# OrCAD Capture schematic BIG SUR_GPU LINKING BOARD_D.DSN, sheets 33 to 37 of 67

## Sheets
33 P33  PCIe x16 Slot-2: size C
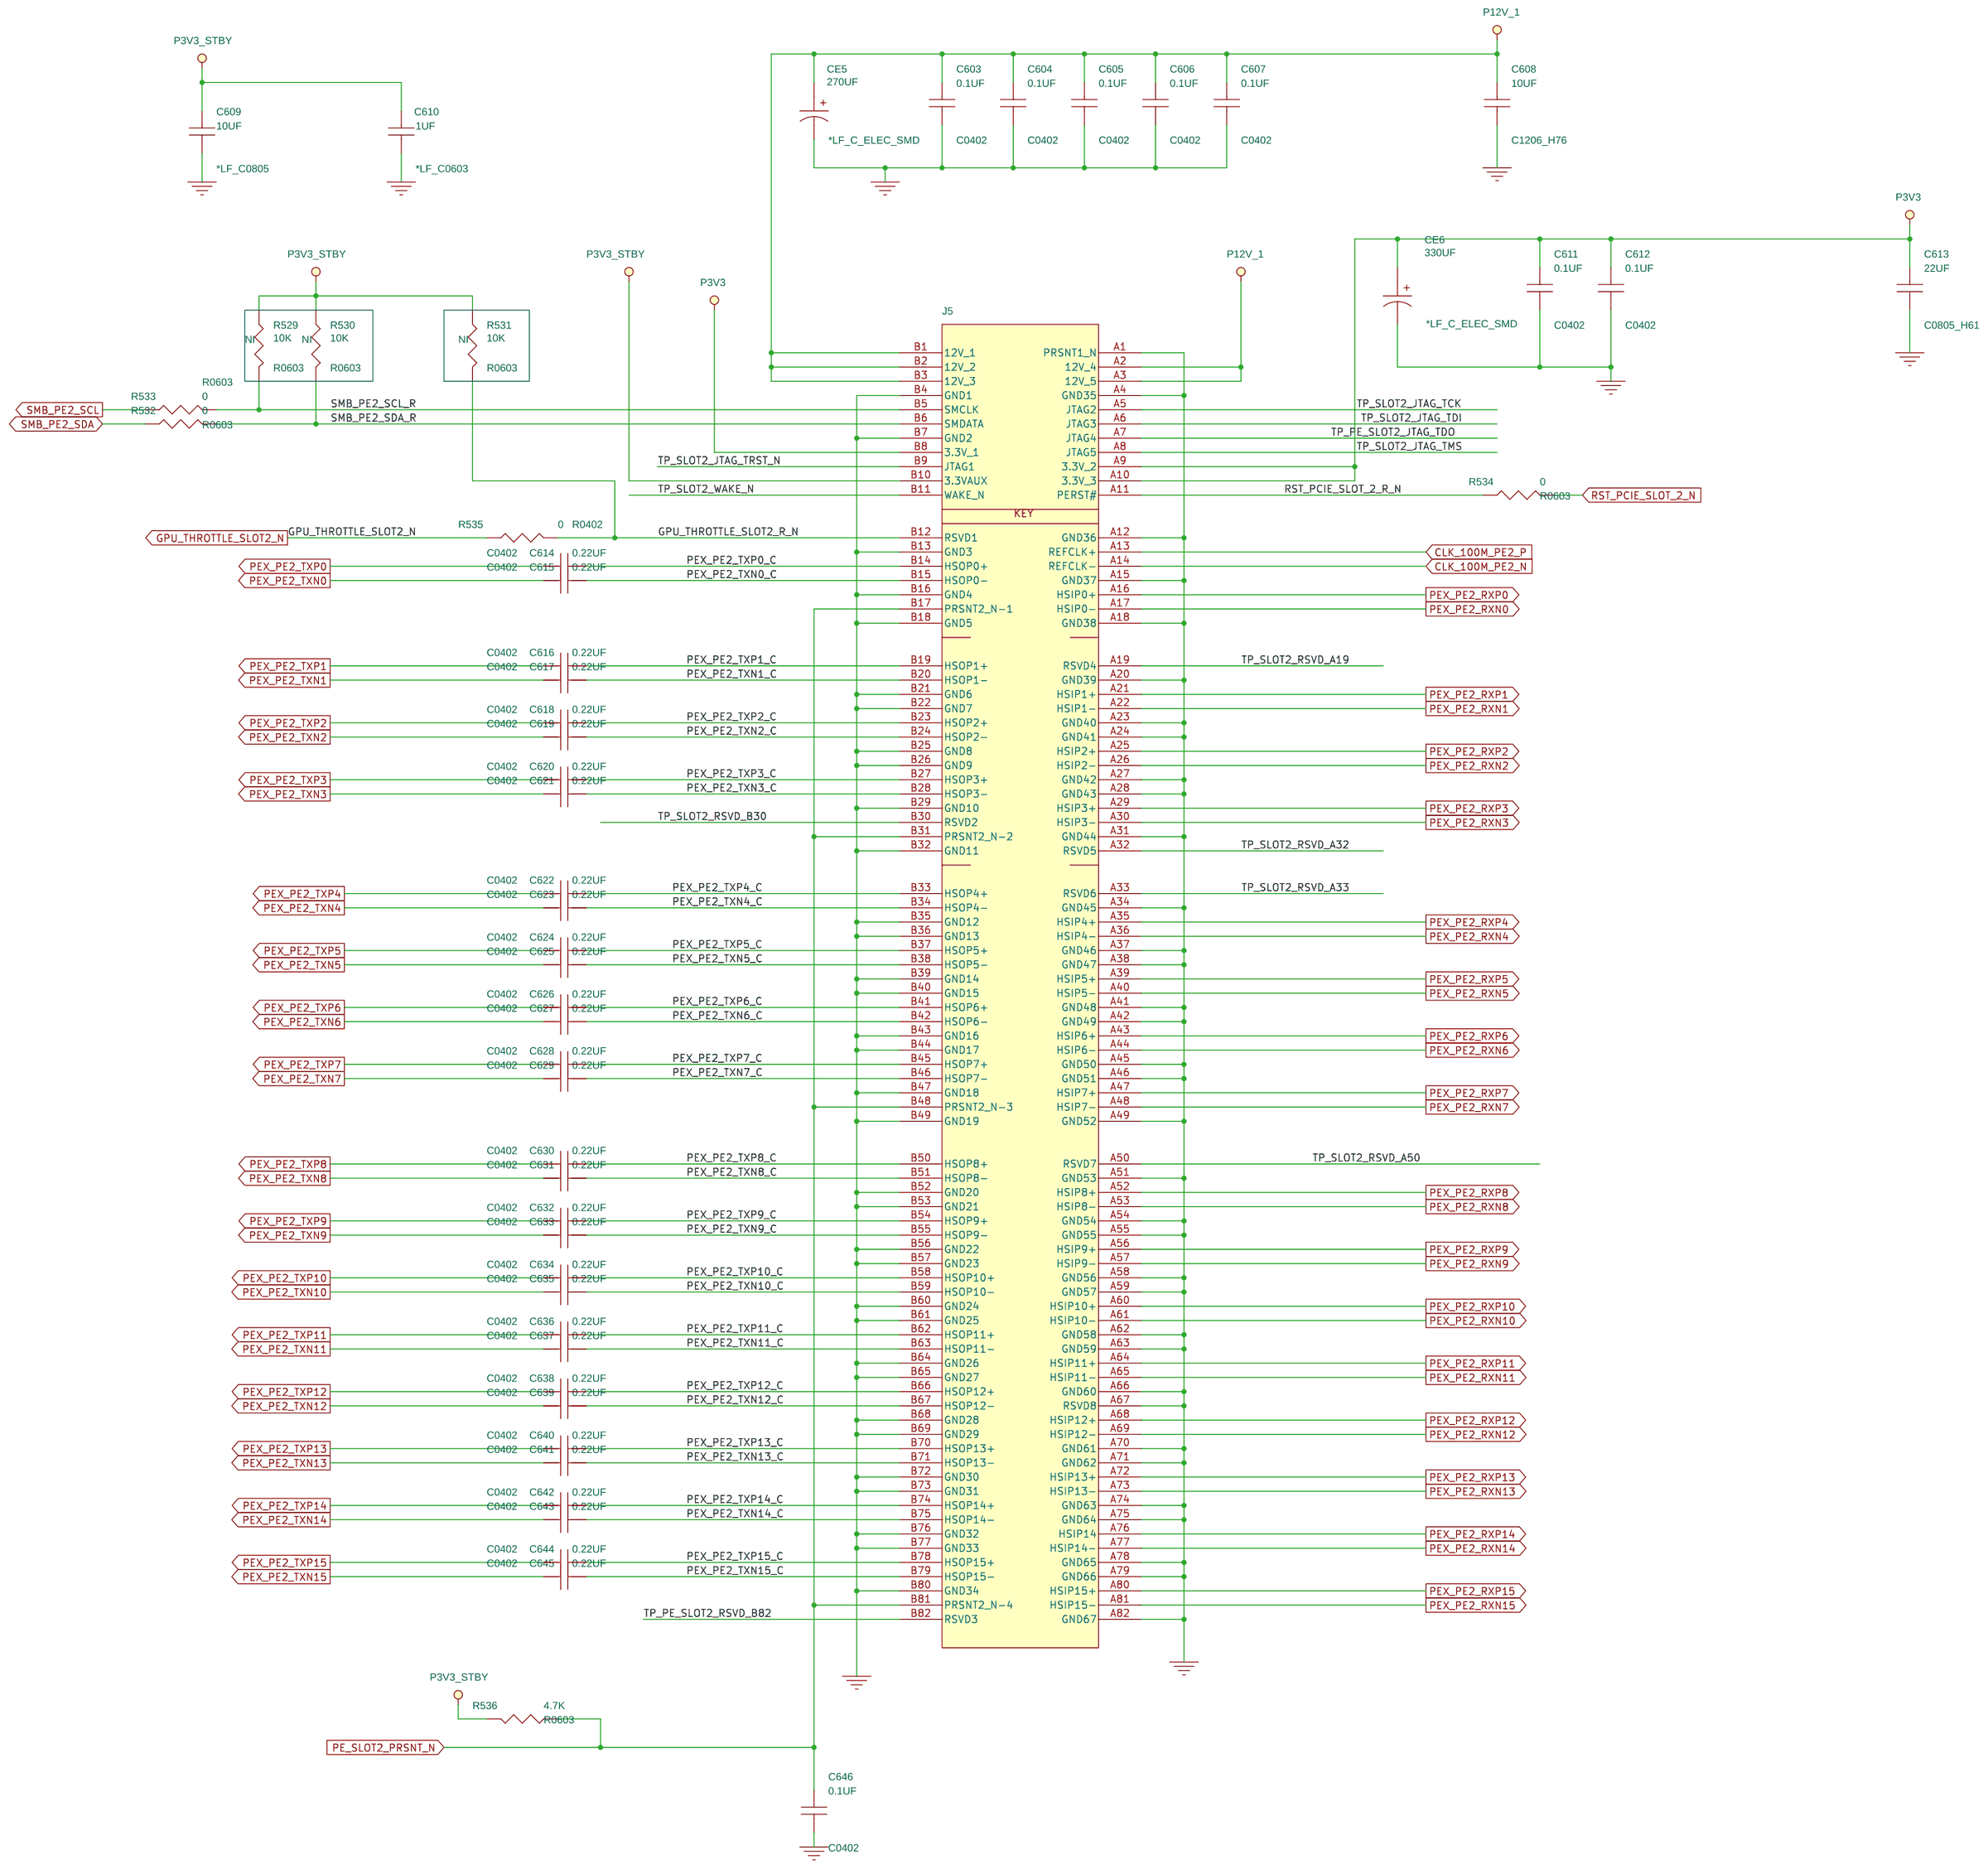
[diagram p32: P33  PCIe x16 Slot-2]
34 P34  PCIe x16 Slot-3: size C
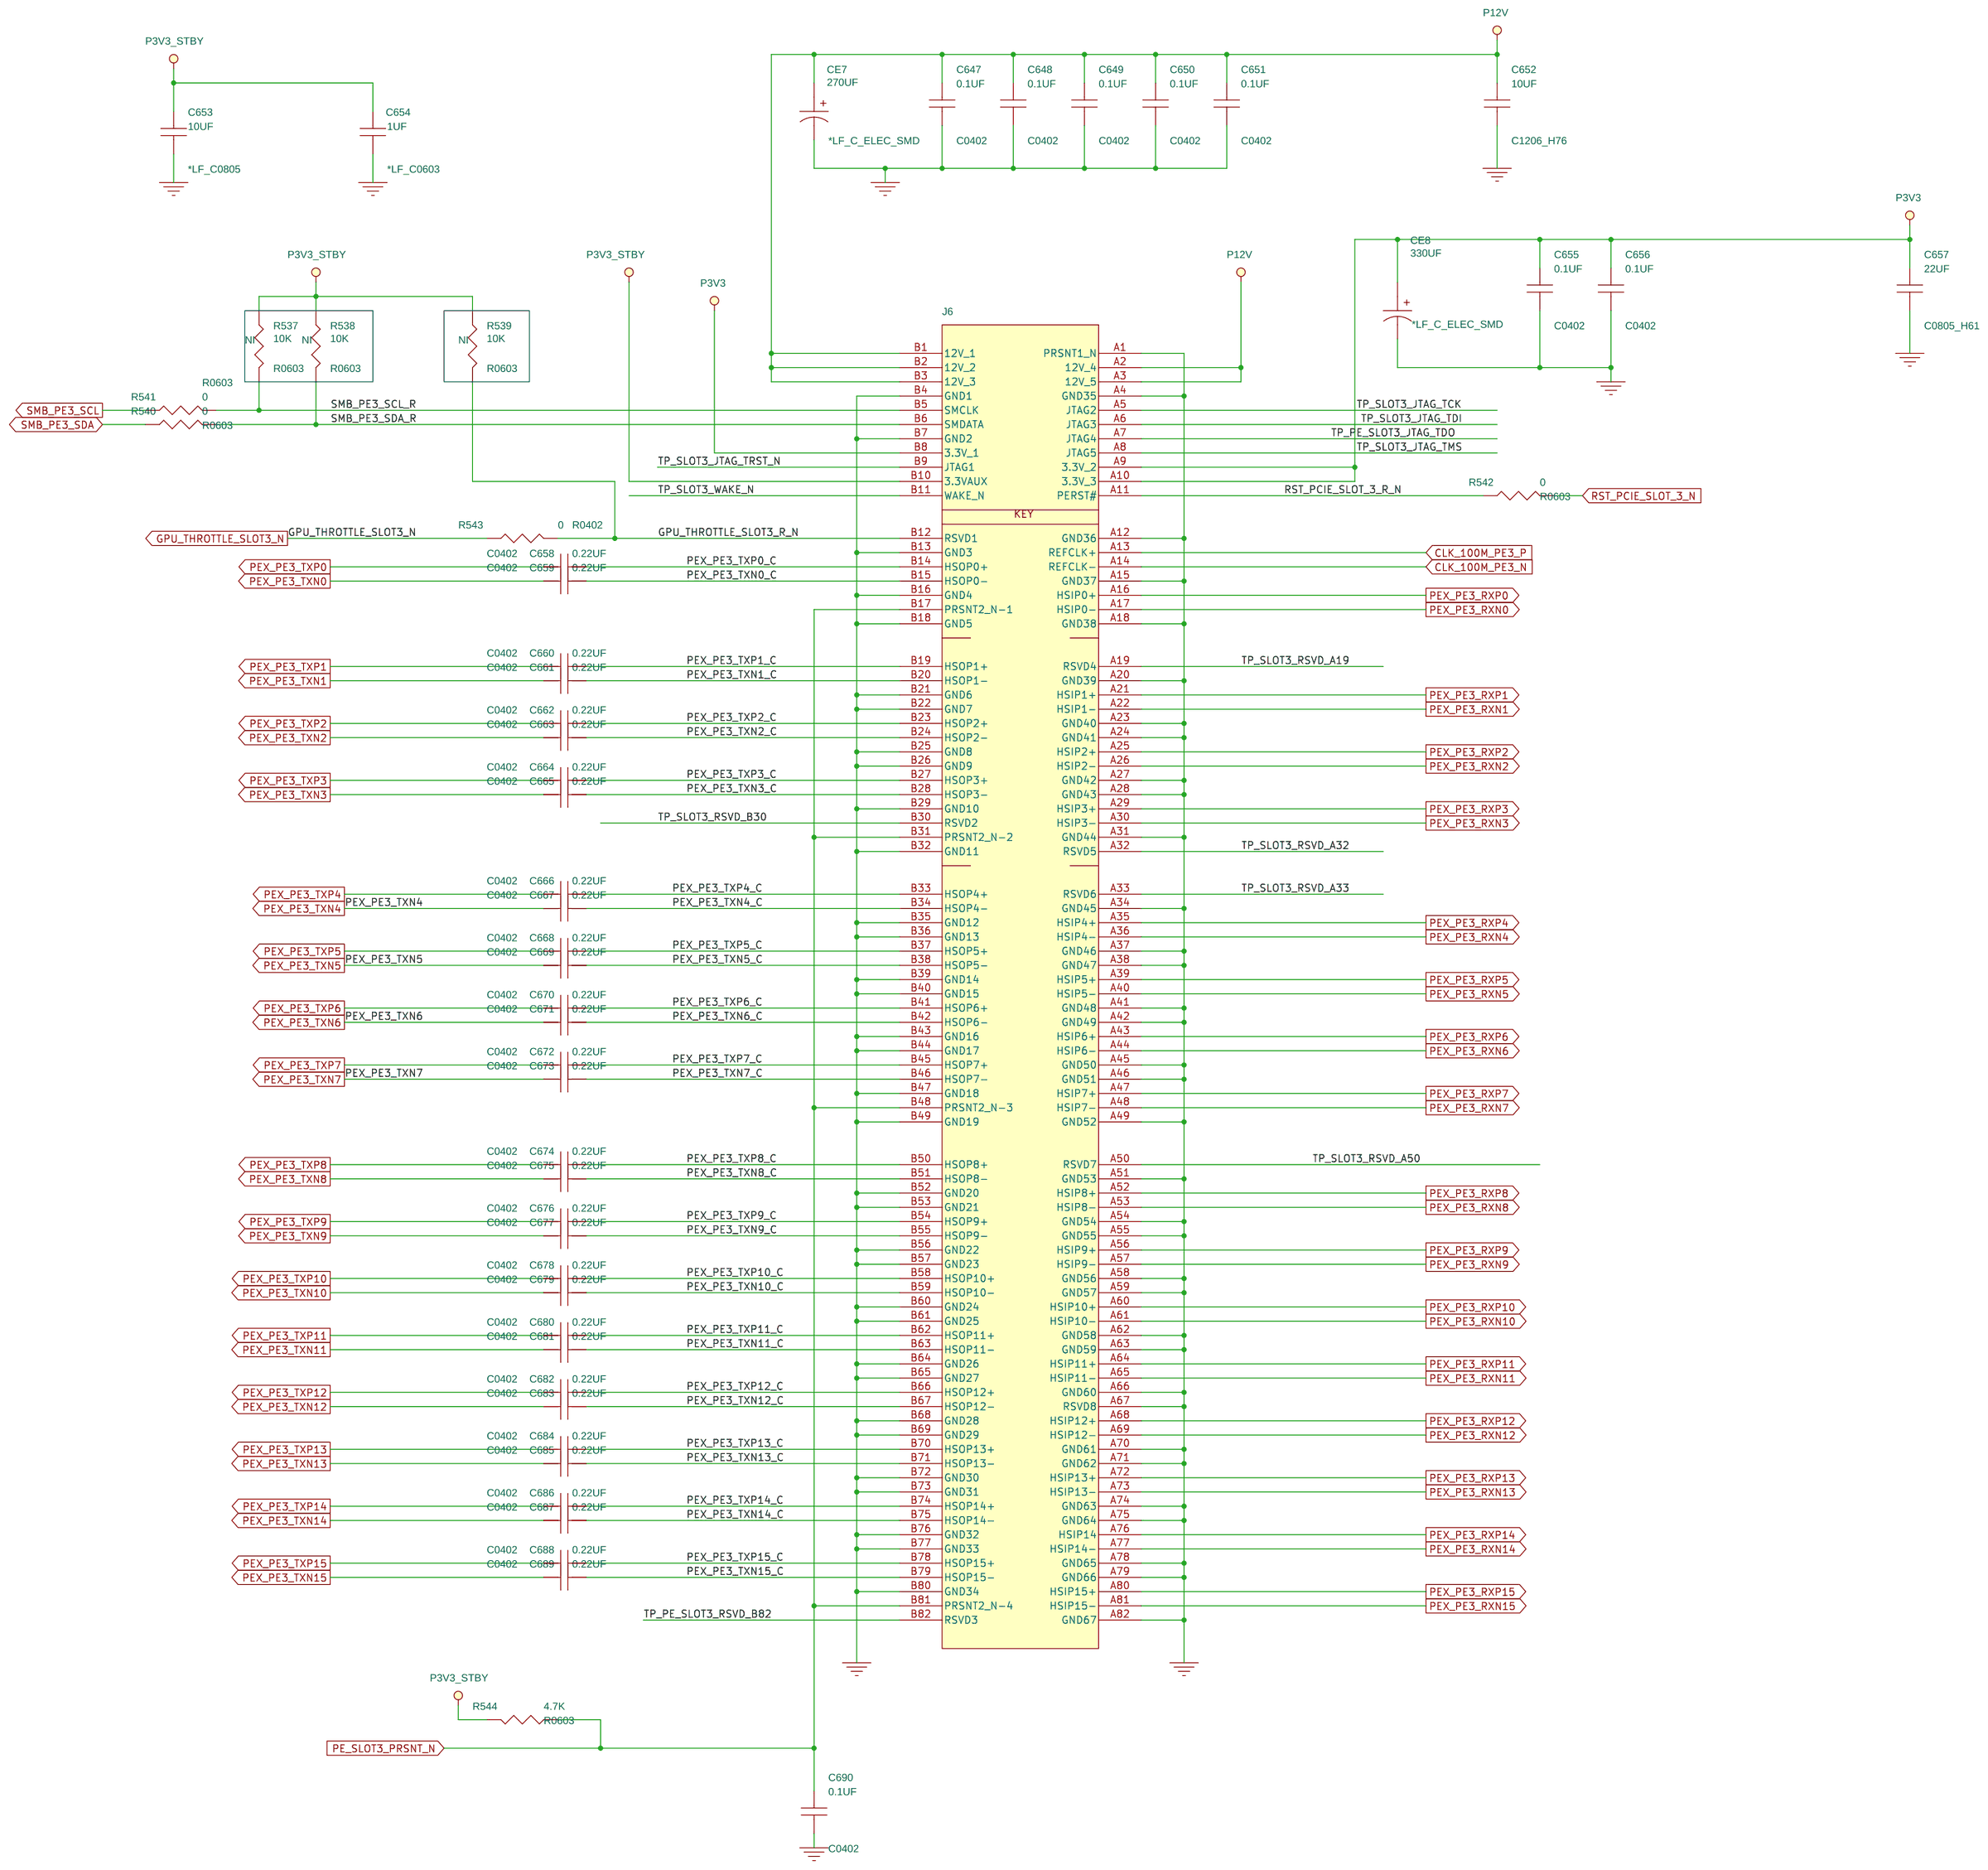
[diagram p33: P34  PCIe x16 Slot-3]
35 P35  PCIe x16 Slot-4: size C
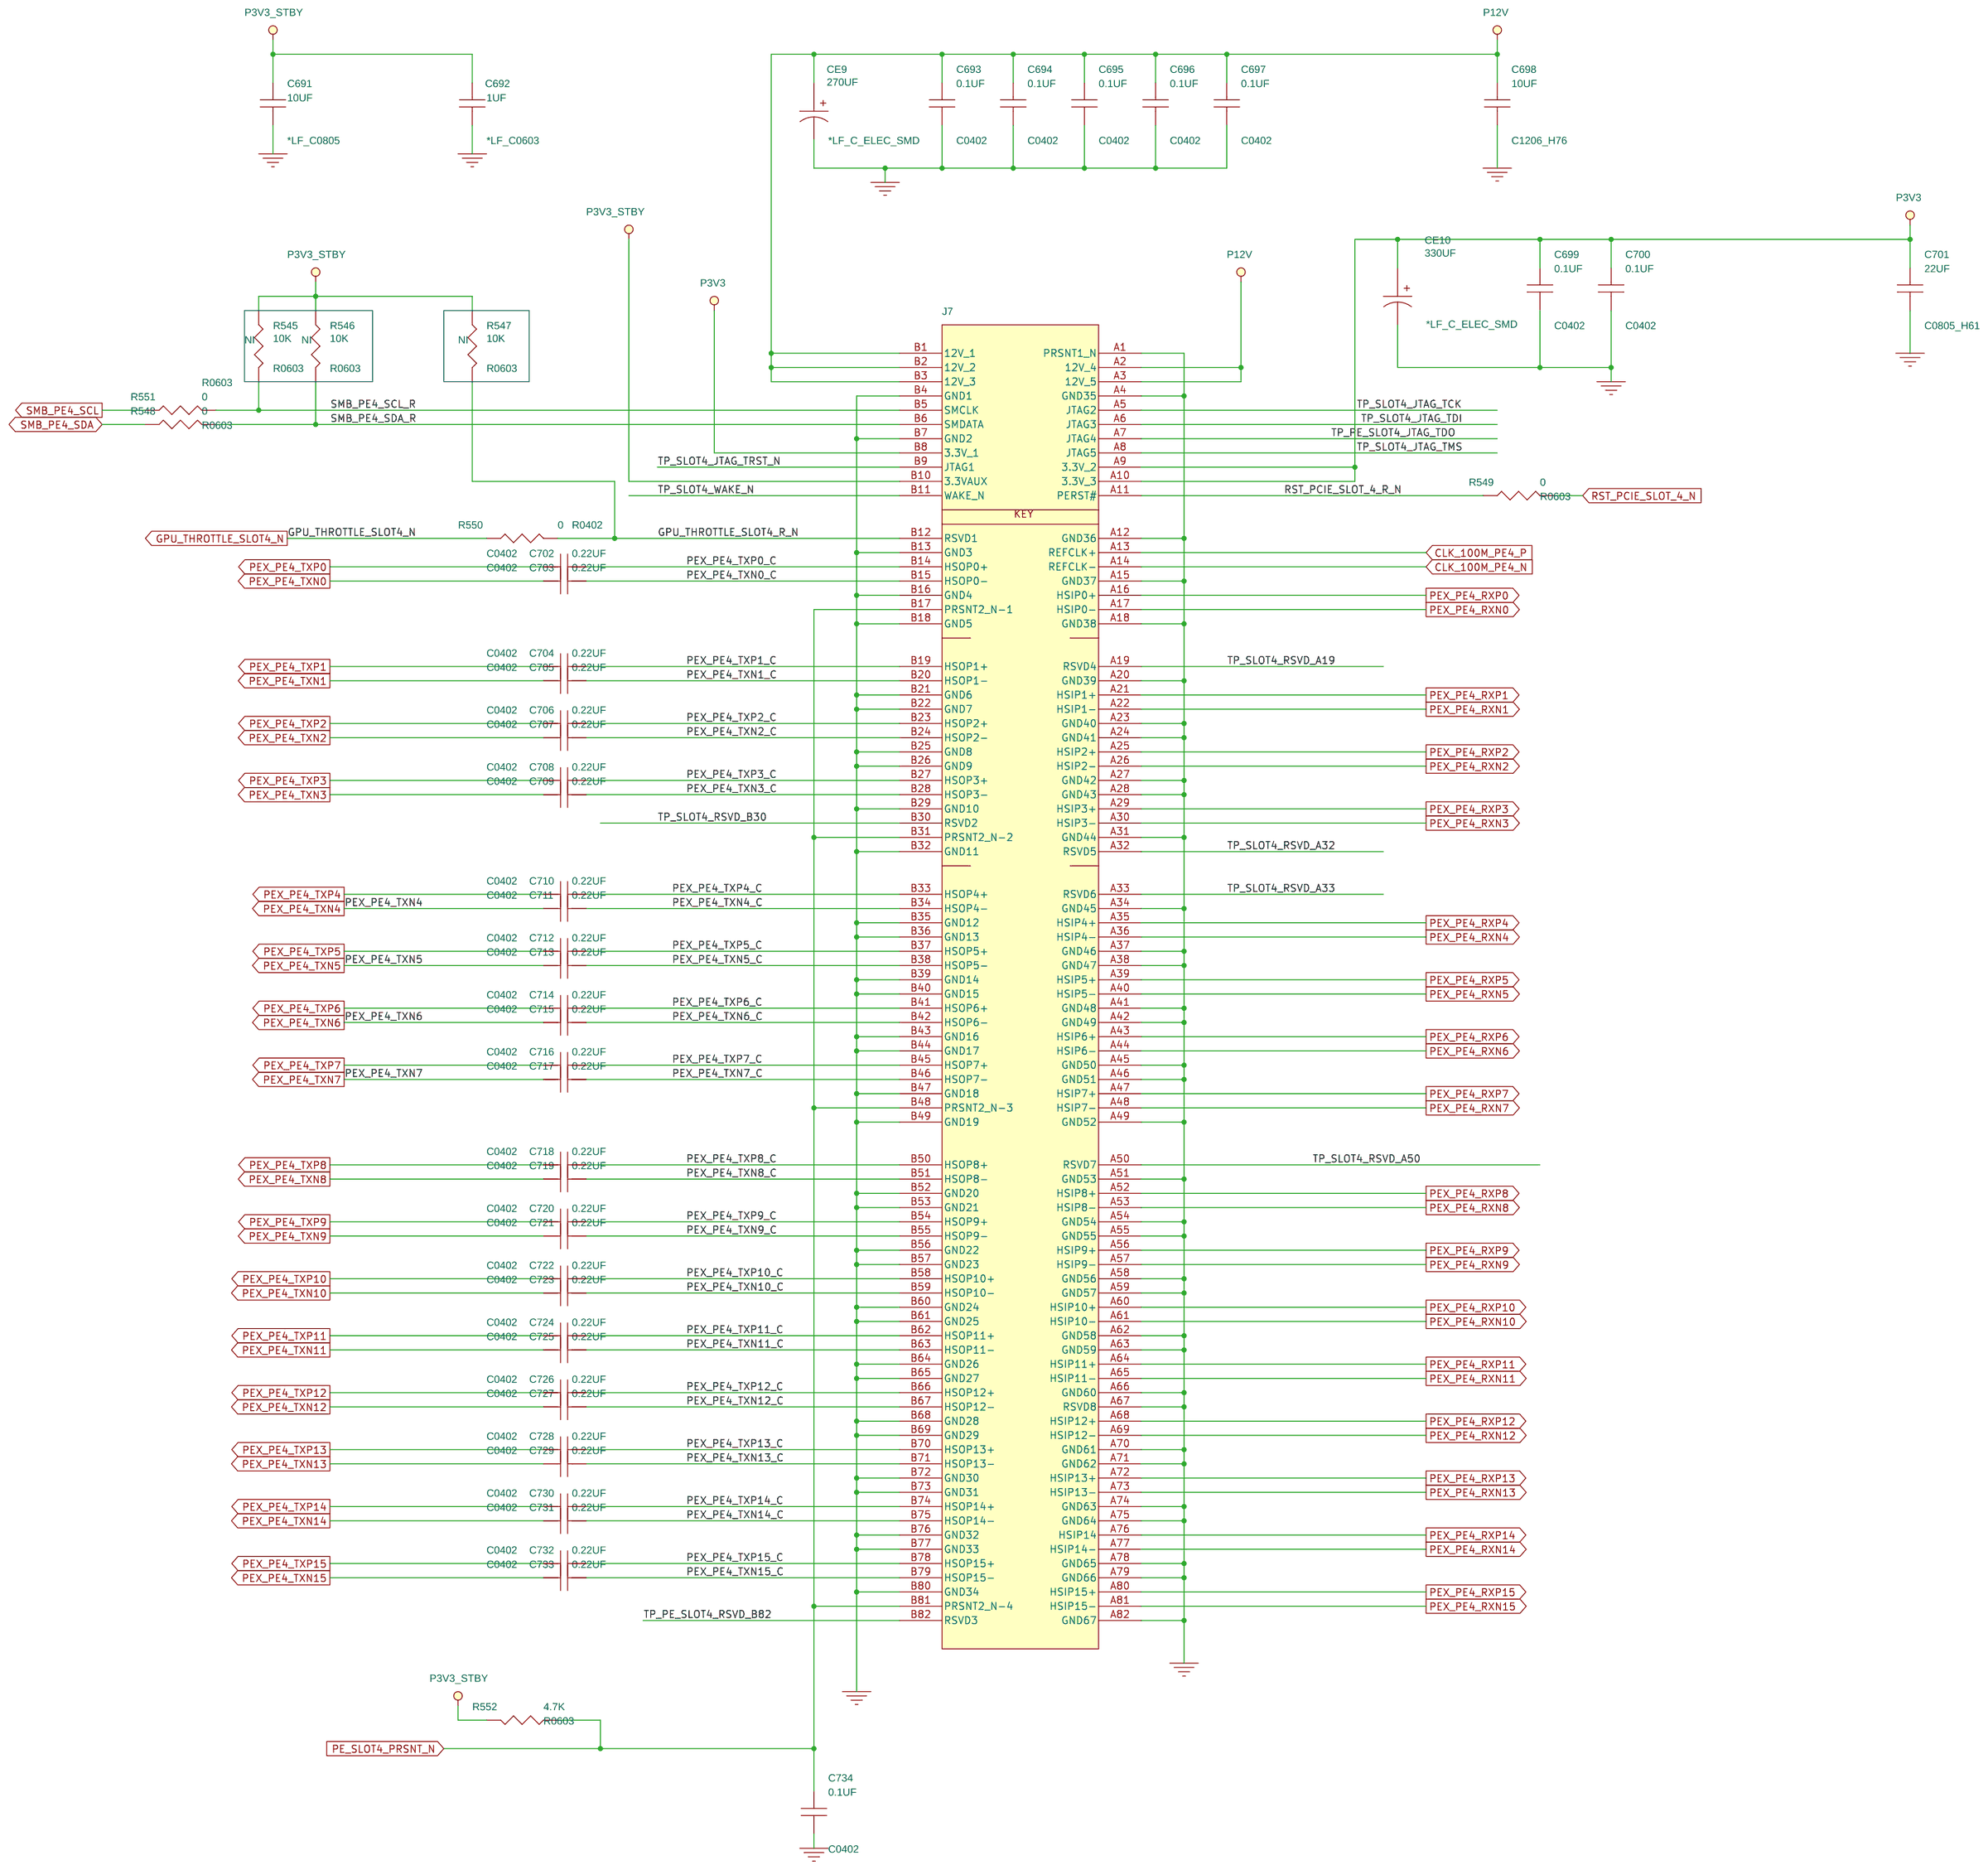
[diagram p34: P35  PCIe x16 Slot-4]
36 P36  PCIe x16 Slot-5: size C
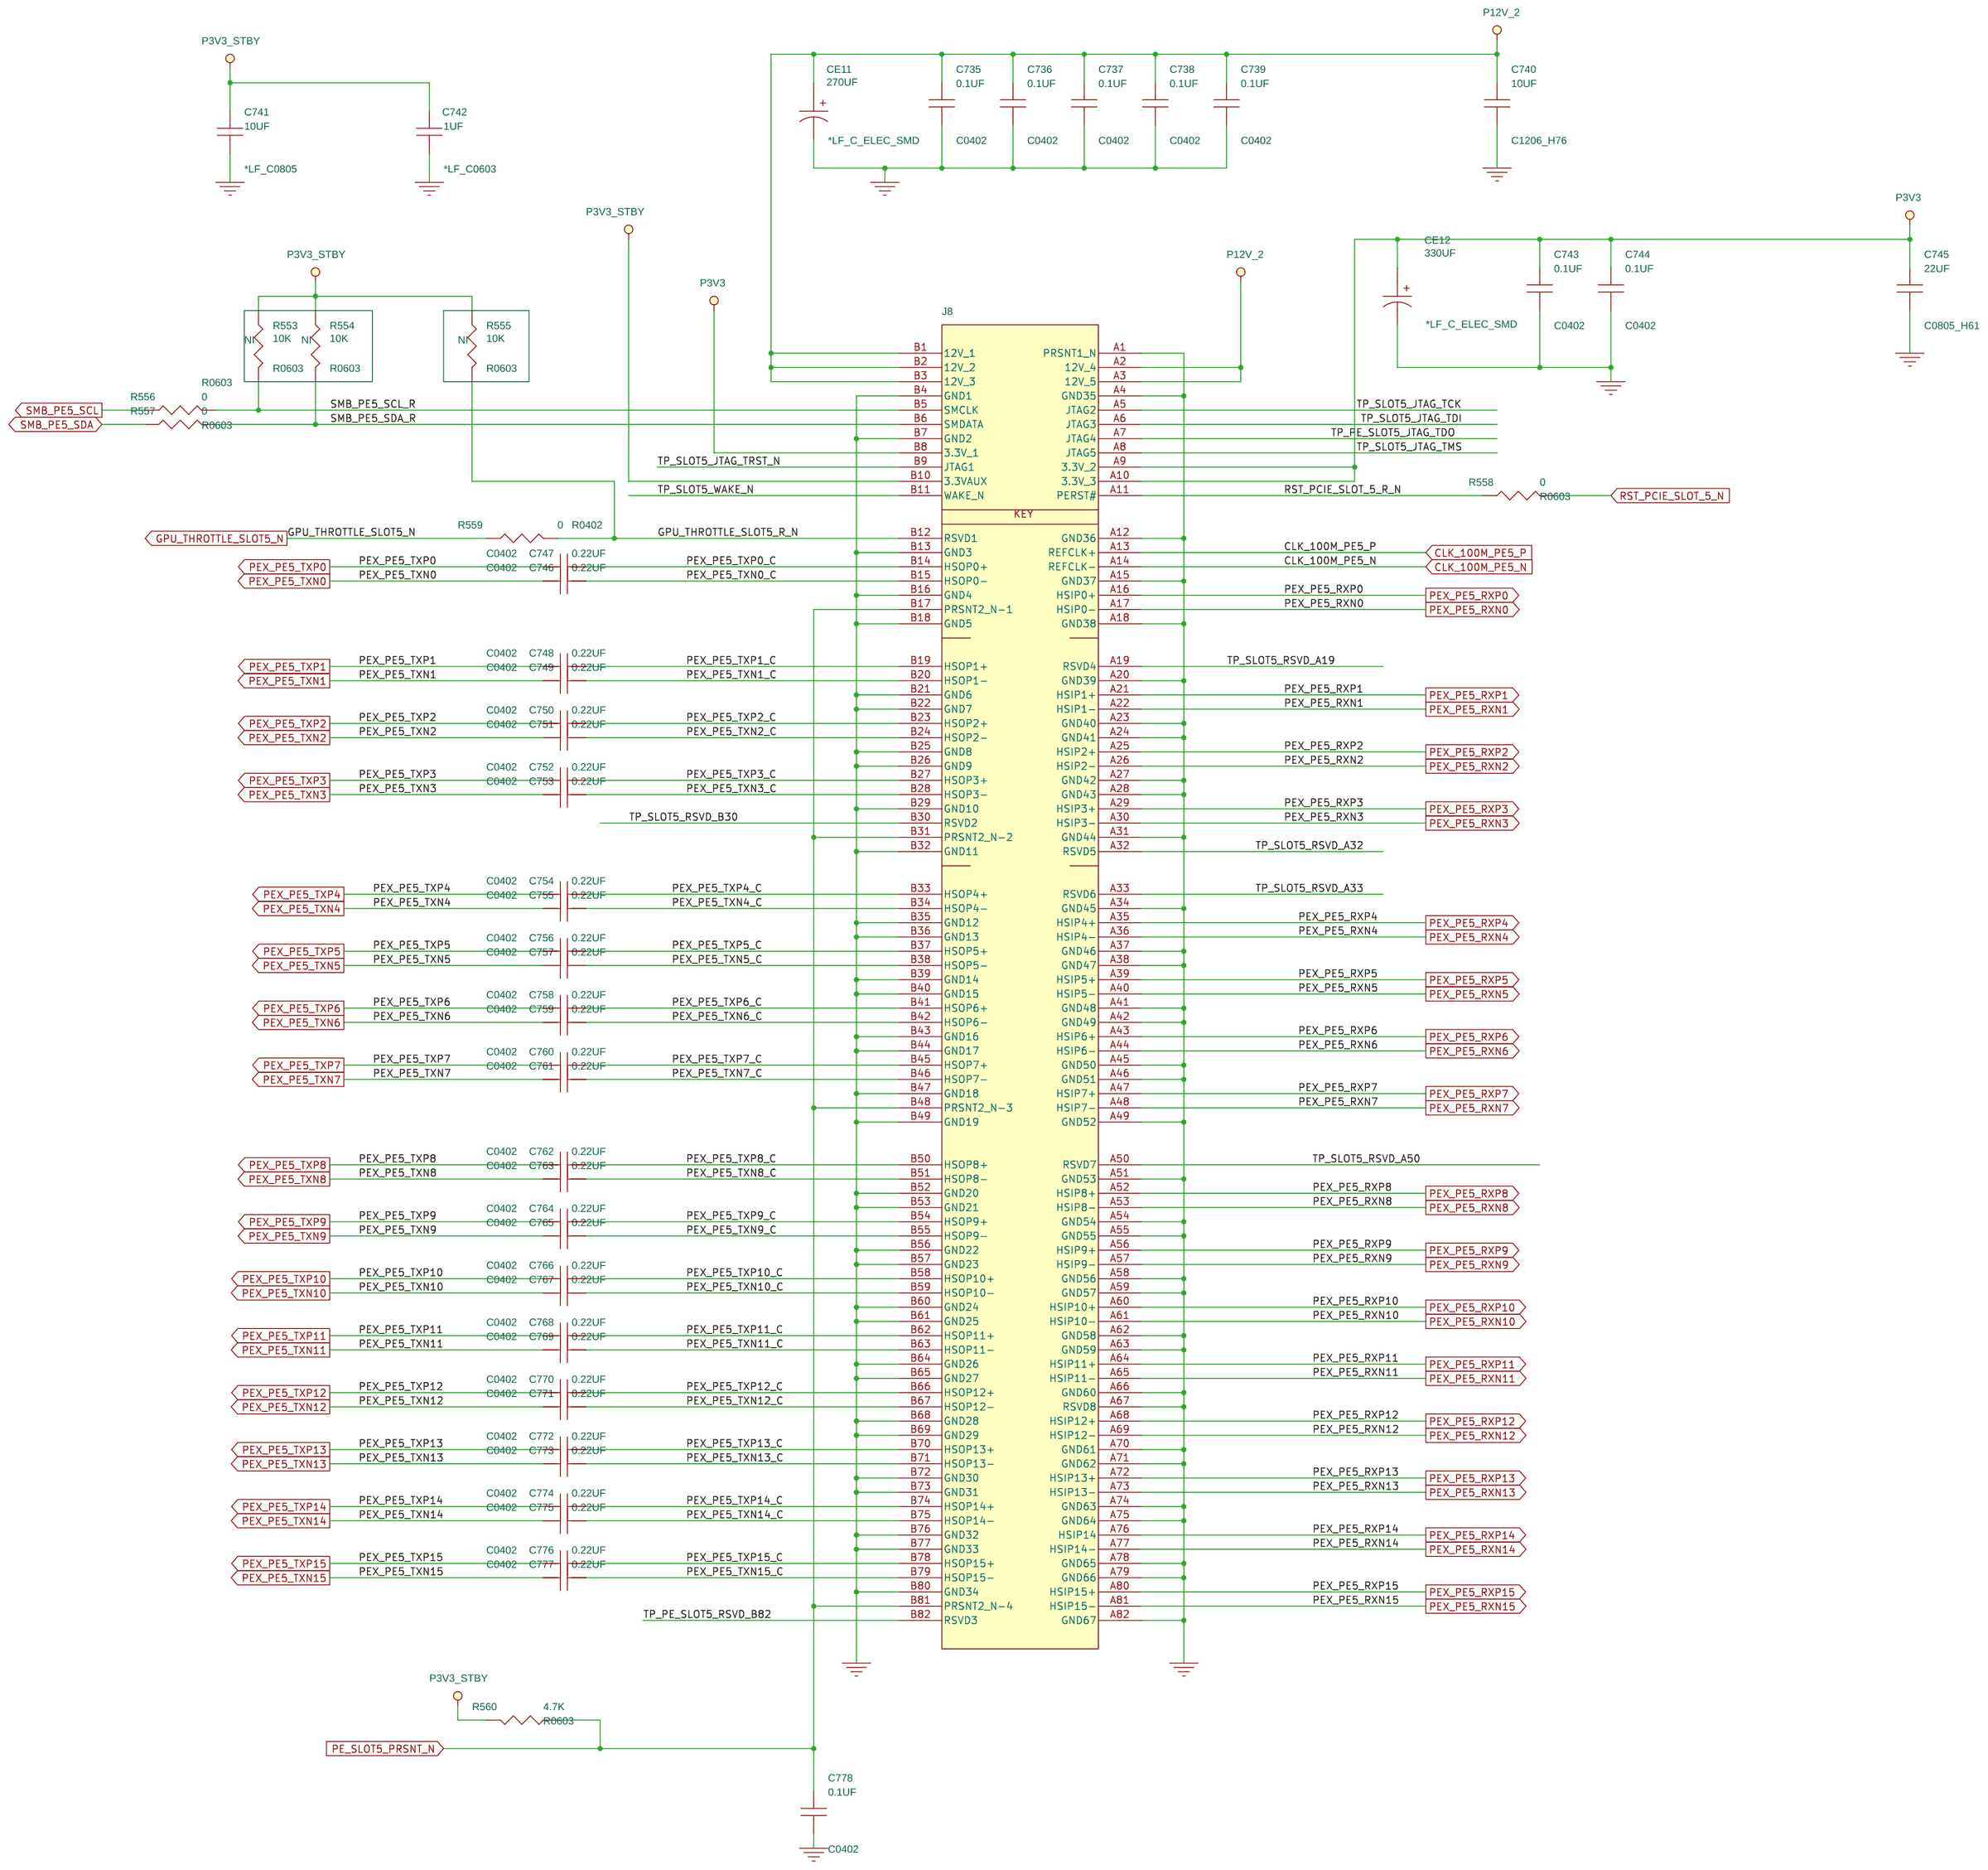
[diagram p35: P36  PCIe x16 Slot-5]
37 P37  PCIe x16 Slot-6: size C
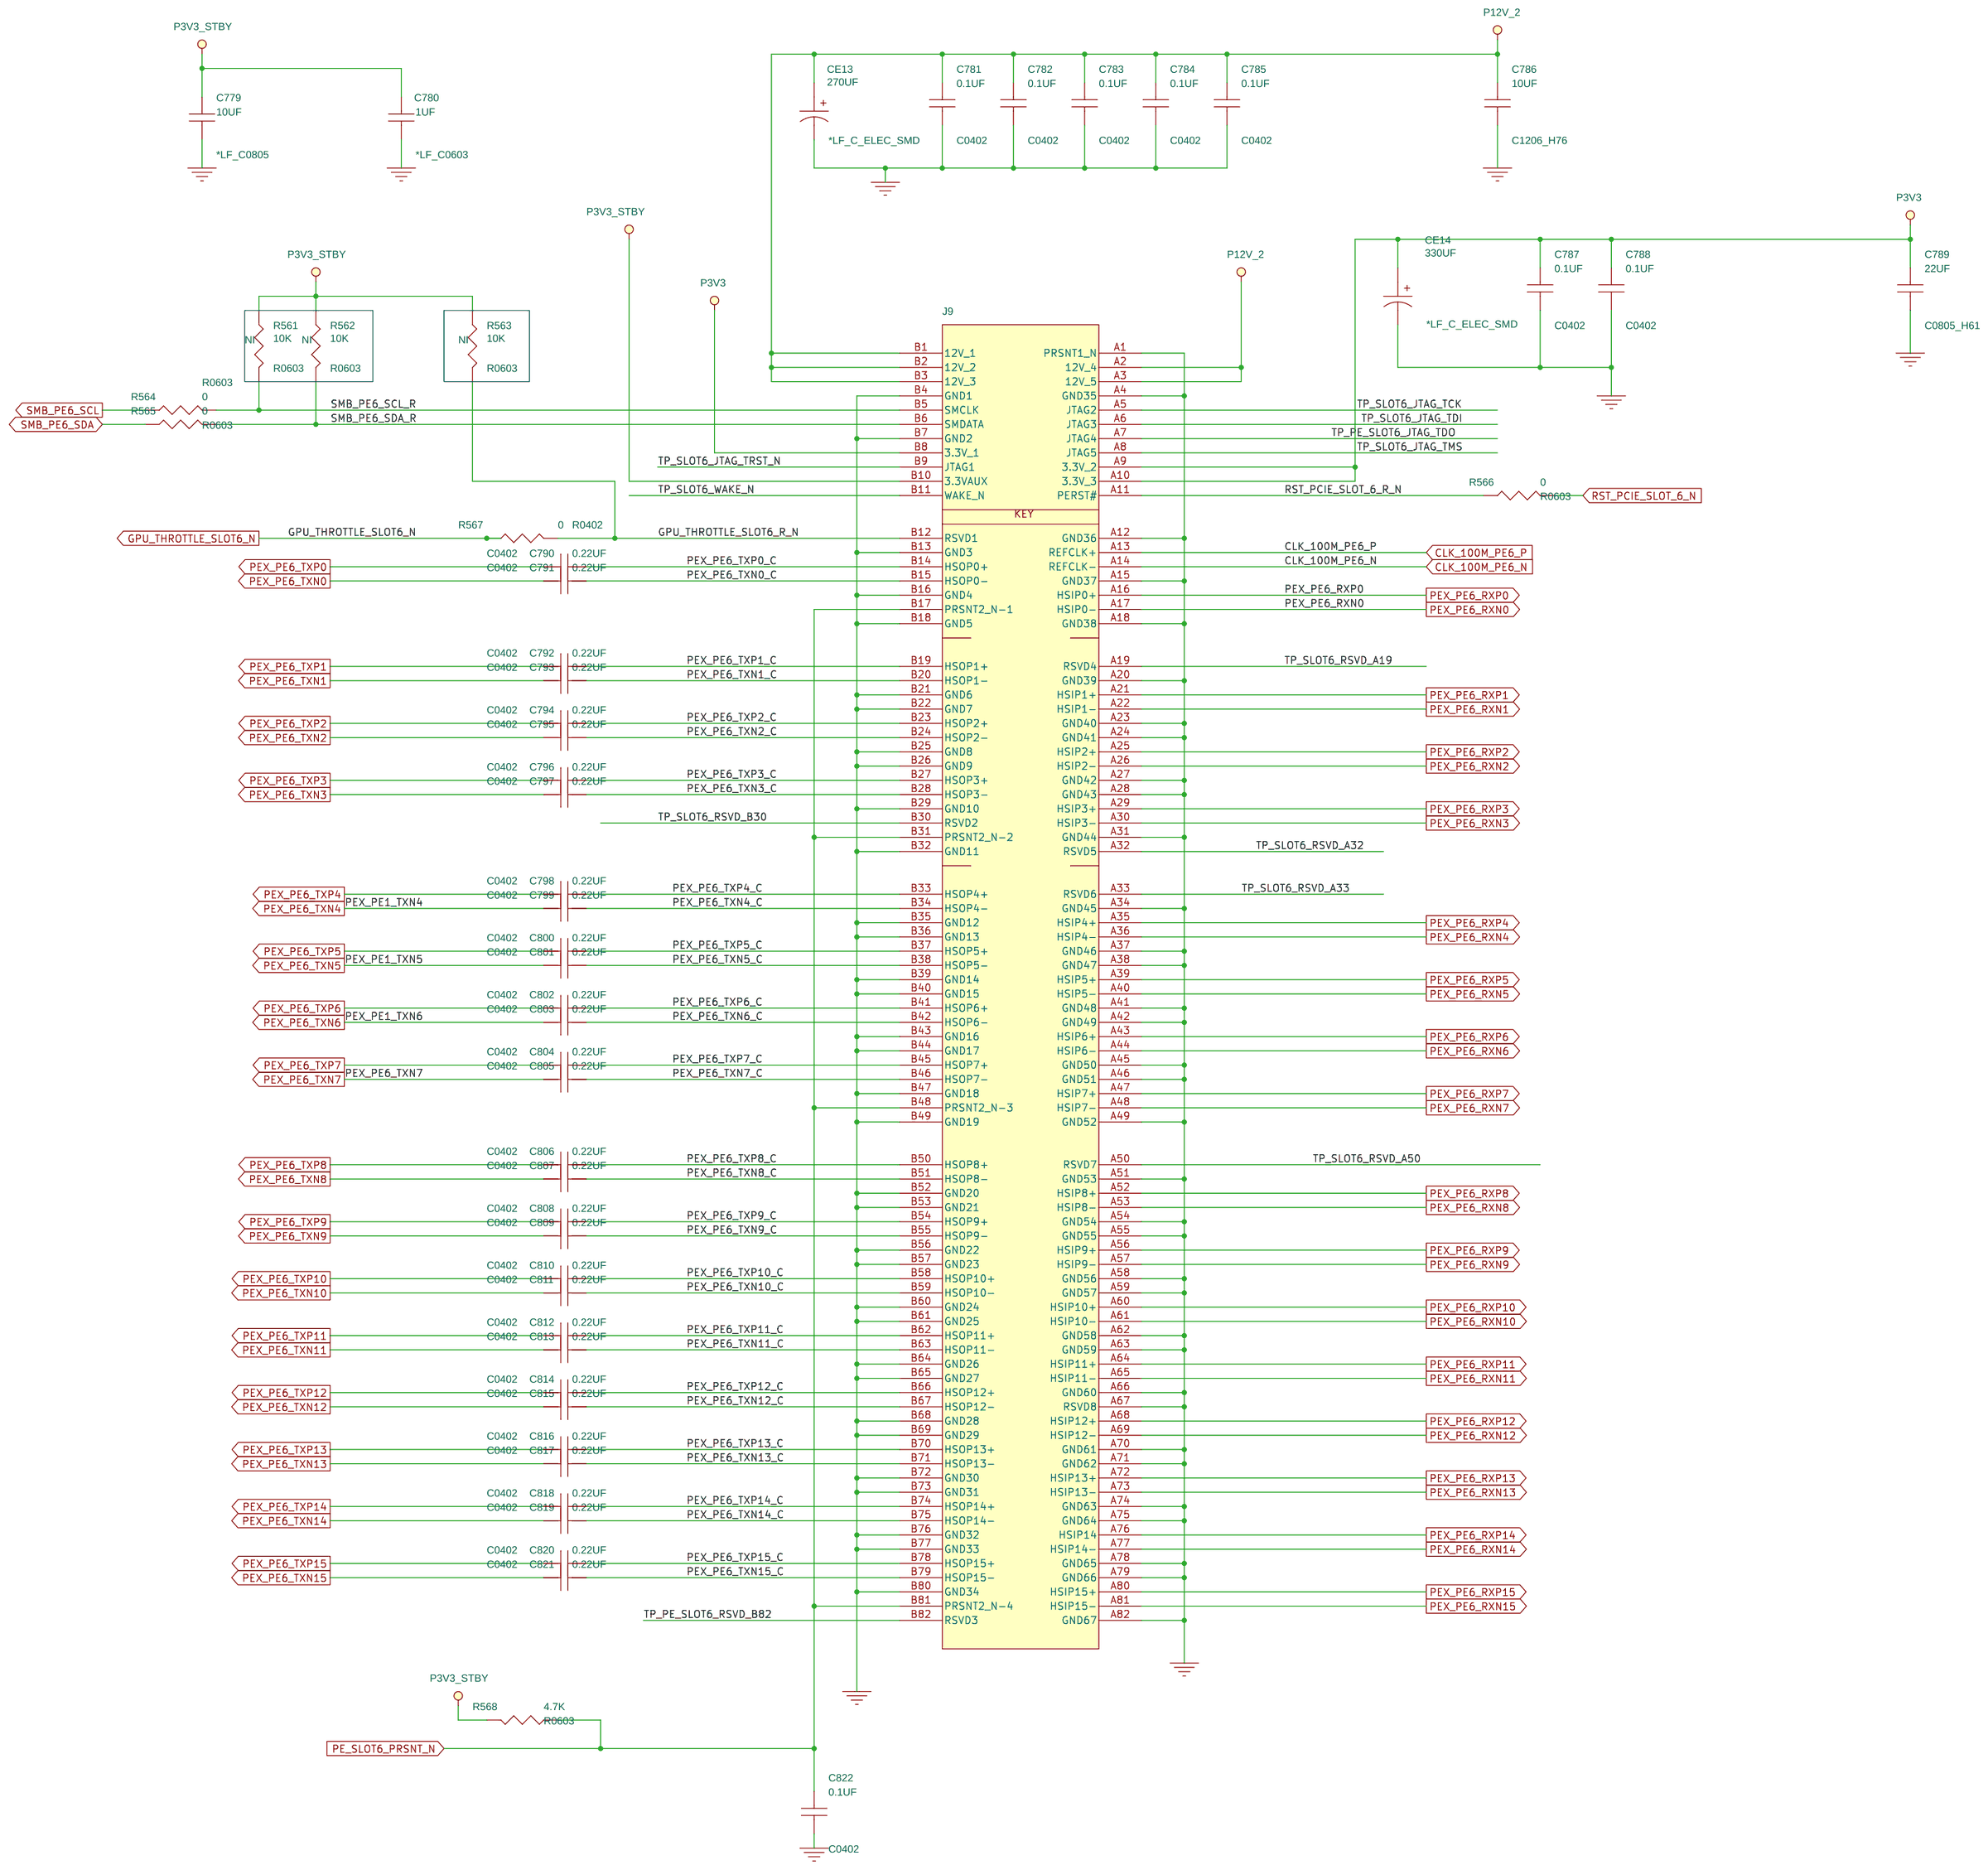
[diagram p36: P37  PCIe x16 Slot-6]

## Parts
sheet P33  PCIe x16 Slot-2
C603  0.1UF  [C0402]
C604  0.1UF  [C0402]
C605  0.1UF  [C0402]
C606  0.1UF  [C0402]
C607  0.1UF  [C0402]
C608  10UF  [C1206_H76]
C609  10UF  [C0805_H61]
C610  1UF  [C0603]
C611  0.1UF  [C0402]
C612  0.1UF  [C0402]
C613  22UF  [C0805_H61]
C614  0.22UF  [C0402]
C615  0.22UF  [C0402]
C616  0.22UF  [C0402]
C617  0.22UF  [C0402]
C618  0.22UF  [C0402]
C619  0.22UF  [C0402]
C620  0.22UF  [C0402]
C621  0.22UF  [C0402]
C622  0.22UF  [C0402]
C623  0.22UF  [C0402]
C624  0.22UF  [C0402]
C625  0.22UF  [C0402]
C626  0.22UF  [C0402]
C627  0.22UF  [C0402]
C628  0.22UF  [C0402]
C629  0.22UF  [C0402]
C630  0.22UF  [C0402]
C631  0.22UF  [C0402]
C632  0.22UF  [C0402]
C633  0.22UF  [C0402]
C634  0.22UF  [C0402]
C635  0.22UF  [C0402]
C636  0.22UF  [C0402]
C637  0.22UF  [C0402]
C638  0.22UF  [C0402]
C639  0.22UF  [C0402]
C640  0.22UF  [C0402]
C641  0.22UF  [C0402]
C642  0.22UF  [C0402]
C643  0.22UF  [C0402]
C644  0.22UF  [C0402]
C645  0.22UF  [C0402]
C646  0.1UF  [C0402]
CE5  270UF  [EC83_248_390S]
CE6  330UF  [EC75_248_229S]
J5  PCIEX16  [G_PCI-E_X16_T2A]
R529  10K  [R0603]
R530  10K  [R0603]
R531  10K  [R0603]
R532  0  [R0603]
R533  0  [R0603]
R534  0  [R0603]
R535  0  [R0402]
R536  4.7K  [R0603]
sheet P34  PCIe x16 Slot-3
C647  0.1UF  [C0402]
C648  0.1UF  [C0402]
C649  0.1UF  [C0402]
C650  0.1UF  [C0402]
C651  0.1UF  [C0402]
C652  10UF  [C1206_H76]
C653  10UF  [C0805_H61]
C654  1UF  [C0603]
C655  0.1UF  [C0402]
C656  0.1UF  [C0402]
C657  22UF  [C0805_H61]
C658  0.22UF  [C0402]
C659  0.22UF  [C0402]
C660  0.22UF  [C0402]
C661  0.22UF  [C0402]
C662  0.22UF  [C0402]
C663  0.22UF  [C0402]
C664  0.22UF  [C0402]
C665  0.22UF  [C0402]
C666  0.22UF  [C0402]
C667  0.22UF  [C0402]
C668  0.22UF  [C0402]
C669  0.22UF  [C0402]
C670  0.22UF  [C0402]
C671  0.22UF  [C0402]
C672  0.22UF  [C0402]
C673  0.22UF  [C0402]
C674  0.22UF  [C0402]
C675  0.22UF  [C0402]
C676  0.22UF  [C0402]
C677  0.22UF  [C0402]
C678  0.22UF  [C0402]
C679  0.22UF  [C0402]
C680  0.22UF  [C0402]
C681  0.22UF  [C0402]
C682  0.22UF  [C0402]
C683  0.22UF  [C0402]
C684  0.22UF  [C0402]
C685  0.22UF  [C0402]
C686  0.22UF  [C0402]
C687  0.22UF  [C0402]
C688  0.22UF  [C0402]
C689  0.22UF  [C0402]
C690  0.1UF  [C0402]
CE7  270UF  [EC83_248_390S]
CE8  330UF  [EC75_248_229S]
J6  PCIEX16  [G_PCI-E_X16_T2A]
R537  10K  [R0603]
R538  10K  [R0603]
R539  10K  [R0603]
R540  0  [R0603]
R541  0  [R0603]
R542  0  [R0603]
R543  0  [R0402]
R544  4.7K  [R0603]
sheet P35  PCIe x16 Slot-4
C691  10UF  [C0805_H61]
C692  1UF  [C0603]
C693  0.1UF  [C0402]
C694  0.1UF  [C0402]
C695  0.1UF  [C0402]
C696  0.1UF  [C0402]
C697  0.1UF  [C0402]
C698  10UF  [C1206_H76]
C699  0.1UF  [C0402]
C700  0.1UF  [C0402]
C701  22UF  [C0805_H61]
C702  0.22UF  [C0402]
C703  0.22UF  [C0402]
C704  0.22UF  [C0402]
C705  0.22UF  [C0402]
C706  0.22UF  [C0402]
C707  0.22UF  [C0402]
C708  0.22UF  [C0402]
C709  0.22UF  [C0402]
C710  0.22UF  [C0402]
C711  0.22UF  [C0402]
C712  0.22UF  [C0402]
C713  0.22UF  [C0402]
C714  0.22UF  [C0402]
C715  0.22UF  [C0402]
C716  0.22UF  [C0402]
C717  0.22UF  [C0402]
C718  0.22UF  [C0402]
C719  0.22UF  [C0402]
C720  0.22UF  [C0402]
C721  0.22UF  [C0402]
C722  0.22UF  [C0402]
C723  0.22UF  [C0402]
C724  0.22UF  [C0402]
C725  0.22UF  [C0402]
C726  0.22UF  [C0402]
C727  0.22UF  [C0402]
C728  0.22UF  [C0402]
C729  0.22UF  [C0402]
C730  0.22UF  [C0402]
C731  0.22UF  [C0402]
C732  0.22UF  [C0402]
C733  0.22UF  [C0402]
C734  0.1UF  [C0402]
CE9  270UF  [EC83_248_390S]
CE10  330UF  [EC75_248_229S]
J7  PCIEX16  [G_PCI-E_X16_T2A]
R545  10K  [R0603]
R546  10K  [R0603]
R547  10K  [R0603]
R548  0  [R0603]
R549  0  [R0603]
R550  0  [R0402]
R551  0  [R0603]
R552  4.7K  [R0603]
sheet P36  PCIe x16 Slot-5
C735  0.1UF  [C0402]
C736  0.1UF  [C0402]
C737  0.1UF  [C0402]
C738  0.1UF  [C0402]
C739  0.1UF  [C0402]
C740  10UF  [C1206_H76]
C741  10UF  [C0805_H61]
C742  1UF  [C0603]
C743  0.1UF  [C0402]
C744  0.1UF  [C0402]
C745  22UF  [C0805_H61]
C746  0.22UF  [C0402]
C747  0.22UF  [C0402]
C748  0.22UF  [C0402]
C749  0.22UF  [C0402]
C750  0.22UF  [C0402]
C751  0.22UF  [C0402]
C752  0.22UF  [C0402]
C753  0.22UF  [C0402]
C754  0.22UF  [C0402]
C755  0.22UF  [C0402]
C756  0.22UF  [C0402]
C757  0.22UF  [C0402]
C758  0.22UF  [C0402]
C759  0.22UF  [C0402]
C760  0.22UF  [C0402]
C761  0.22UF  [C0402]
C762  0.22UF  [C0402]
C763  0.22UF  [C0402]
C764  0.22UF  [C0402]
C765  0.22UF  [C0402]
C766  0.22UF  [C0402]
C767  0.22UF  [C0402]
C768  0.22UF  [C0402]
C769  0.22UF  [C0402]
C770  0.22UF  [C0402]
C771  0.22UF  [C0402]
C772  0.22UF  [C0402]
C773  0.22UF  [C0402]
C774  0.22UF  [C0402]
C775  0.22UF  [C0402]
C776  0.22UF  [C0402]
C777  0.22UF  [C0402]
C778  0.1UF  [C0402]
CE11  270UF  [EC83_248_390S]
CE12  330UF  [EC75_248_229S]
J8  PCIEX16  [G_PCI-E_X16_T2A]
R553  10K  [R0603]
R554  10K  [R0603]
R555  10K  [R0603]
R556  0  [R0603]
R557  0  [R0603]
R558  0  [R0603]
R559  0  [R0402]
R560  4.7K  [R0603]
sheet P37  PCIe x16 Slot-6
C779  10UF  [C0805_H61]
C780  1UF  [C0603]
C781  0.1UF  [C0402]
C782  0.1UF  [C0402]
C783  0.1UF  [C0402]
C784  0.1UF  [C0402]
C785  0.1UF  [C0402]
C786  10UF  [C1206_H76]
C787  0.1UF  [C0402]
C788  0.1UF  [C0402]
C789  22UF  [C0805_H61]
C790  0.22UF  [C0402]
C791  0.22UF  [C0402]
C792  0.22UF  [C0402]
C793  0.22UF  [C0402]
C794  0.22UF  [C0402]
C795  0.22UF  [C0402]
C796  0.22UF  [C0402]
C797  0.22UF  [C0402]
C798  0.22UF  [C0402]
C799  0.22UF  [C0402]
C800  0.22UF  [C0402]
C801  0.22UF  [C0402]
C802  0.22UF  [C0402]
C803  0.22UF  [C0402]
C804  0.22UF  [C0402]
C805  0.22UF  [C0402]
C806  0.22UF  [C0402]
C807  0.22UF  [C0402]
C808  0.22UF  [C0402]
C809  0.22UF  [C0402]
C810  0.22UF  [C0402]
C811  0.22UF  [C0402]
C812  0.22UF  [C0402]
C813  0.22UF  [C0402]
C814  0.22UF  [C0402]
C815  0.22UF  [C0402]
C816  0.22UF  [C0402]
C817  0.22UF  [C0402]
C818  0.22UF  [C0402]
C819  0.22UF  [C0402]
C820  0.22UF  [C0402]
C821  0.22UF  [C0402]
C822  0.1UF  [C0402]
CE13  270UF  [EC83_248_390S]
CE14  330UF  [EC75_248_229S]
J9  PCIEX16  [G_PCI-E_X16_T2A]
R561  10K  [R0603]
R562  10K  [R0603]
R563  10K  [R0603]
R564  0  [R0603]
R565  0  [R0603]
R566  0  [R0603]
R567  0  [R0402]
R568  4.7K  [R0603]

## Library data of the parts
C603-C607 C611 C612 C614-C651 C655 C656 C658-C690 C693-C697 C699 C700 C702-C739 C743 C744 C746-C778 C781-C785 C787 C788 C790-C822 = CAP_NP: Part_Type: *LF_C0402
C608 C652 C698 C740 C786 = CAP_NP: Part_Type: *LF_C1206
C609 C613 C653 C657 C691 C701 C741 C745 C779 C789 = CAP_NP: Part_Type: *LF_C0805
C610 C654 C692 C742 C780 = CAP_NP: Part_Type: *LF_C0603
CE5-CE14 = CAPACITOR_POL: Part_Type: *LF_C_ELEC_SMD
J5-J9 = PCI_EXPRESS_X16_CONN: DIP_SMD: DIP; Part_Type: *LF_Connector
R529-R531 R537-R539 R545-R547 R553-R555 R561-R563 = R: Not_insert: NI; Part_Type: *LF_Resistor; WATTAGE: 1/10W
R532-R534 R536 R540-R542 R544 R548 R549 R551 R552 R556-R558 R560 R564-R566 R568 = R: Part_Type: *LF_Resistor; WATTAGE: 1/10W
R535 R543 R550 R559 R567 = R: Part_Type: *LF_Resistor; WATTAGE: 1/16W

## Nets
GND: C603.2 C604.2 C605.2 C606.2 C607.2 C608.2 C609.2 C610.2 C611.2 C612.2 C613.2 C646.2 C647.2 C648.2 C649.2 C650.2 C651.2 C652.2 C653.2 C654.2 C655.2 C656.2 C657.2 C690.2 C691.2 C692.2 C693.2 C694.2 C695.2 C696.2 C697.2 C698.2 C699.2 C700.2 C701.2 C734.2 C735.2 C736.2 C737.2 C738.2 C739.2 C740.2 C741.2 C742.2 C743.2 C744.2 C745.2 C778.2 C779.2 C780.2 C781.2 C782.2 C783.2 C784.2 C785.2 C786.2 C787.2 C788.2 C789.2 C822.2 CE5.2 CE6.2 CE7.2 CE8.2 CE9.2 CE10.2 CE11.2 CE12.2 CE13.2 CE14.2 J5.A1(PRSNT1_N) J5.A4(GND35) J5.A12(GND36) J5.A15(GND37) J5.A18(GND38) J5.A20(GND39) J5.A23(GND40) J5.A24(GND41) J5.A27(GND42) J5.A28(GND43) J5.A31(GND44) J5.A34(GND45) J5.A37(GND46) J5.A38(GND47) J5.A41(GND48) J5.A42(GND49) J5.A45(GND50) J5.A46(GND51) J5.A49(GND52) J5.A51(GND53) J5.A54(GND54) J5.A55(GND55) J5.A58(GND56) J5.A59(GND57) J5.A62(GND58) J5.A63(GND59) J5.A66(GND60) J5.A67(RSVD8) J5.A70(GND61) J5.A71(GND62) J5.A74(GND63) J5.A75(GND64) J5.A78(GND65) J5.A79(GND66) J5.A82(GND67) J5.B4(GND1) J5.B7(GND2) J5.B13(GND3) J5.B16(GND4) J5.B18(GND5) J5.B21(GND6) J5.B22(GND7) J5.B25(GND8) J5.B26(GND9) J5.B29(GND10) J5.B32(GND11) J5.B35(GND12) J5.B36(GND13) J5.B39(GND14) J5.B40(GND15) J5.B43(GND16) J5.B44(GND17) J5.B47(GND18) J5.B49(GND19) J5.B52(GND20) J5.B53(GND21) J5.B56(GND22) J5.B57(GND23) J5.B60(GND24) J5.B61(GND25) J5.B64(GND26) J5.B65(GND27) J5.B68(GND28) J5.B69(GND29) J5.B72(GND30) J5.B73(GND31) J5.B76(GND32) J5.B77(GND33) J5.B80(GND34) J6.A1(PRSNT1_N) J6.A4(GND35) J6.A12(GND36) J6.A15(GND37) J6.A18(GND38) J6.A20(GND39) J6.A23(GND40) J6.A24(GND41) J6.A27(GND42) J6.A28(GND43) J6.A31(GND44) J6.A34(GND45) J6.A37(GND46) J6.A38(GND47) J6.A41(GND48) J6.A42(GND49) J6.A45(GND50) J6.A46(GND51) J6.A49(GND52) J6.A51(GND53) J6.A54(GND54) J6.A55(GND55) J6.A58(GND56) J6.A59(GND57) J6.A62(GND58) J6.A63(GND59) J6.A66(GND60) J6.A67(RSVD8) J6.A70(GND61) J6.A71(GND62) J6.A74(GND63) J6.A75(GND64) J6.A78(GND65) J6.A79(GND66) J6.A82(GND67) J6.B4(GND1) J6.B7(GND2) J6.B13(GND3) J6.B16(GND4) J6.B18(GND5) J6.B21(GND6) J6.B22(GND7) J6.B25(GND8) J6.B26(GND9) J6.B29(GND10) J6.B32(GND11) J6.B35(GND12) J6.B36(GND13) J6.B39(GND14) J6.B40(GND15) J6.B43(GND16) J6.B44(GND17) J6.B47(GND18) J6.B49(GND19) J6.B52(GND20) J6.B53(GND21) J6.B56(GND22) J6.B57(GND23) J6.B60(GND24) J6.B61(GND25) J6.B64(GND26) J6.B65(GND27) J6.B68(GND28) J6.B69(GND29) J6.B72(GND30) J6.B73(GND31) J6.B76(GND32) J6.B77(GND33) J6.B80(GND34) J7.A1(PRSNT1_N) J7.A4(GND35) J7.A12(GND36) J7.A15(GND37) J7.A18(GND38) J7.A20(GND39) J7.A23(GND40) J7.A24(GND41) J7.A27(GND42) J7.A28(GND43) J7.A31(GND44) J7.A34(GND45) J7.A37(GND46) J7.A38(GND47) J7.A41(GND48) J7.A42(GND49) J7.A45(GND50) J7.A46(GND51) J7.A49(GND52) J7.A51(GND53) J7.A54(GND54) J7.A55(GND55) J7.A58(GND56) J7.A59(GND57) J7.A62(GND58) J7.A63(GND59) J7.A66(GND60) J7.A67(RSVD8) J7.A70(GND61) J7.A71(GND62) J7.A74(GND63) J7.A75(GND64) J7.A78(GND65) J7.A79(GND66) J7.A82(GND67) J7.B4(GND1) J7.B7(GND2) J7.B13(GND3) J7.B16(GND4) J7.B18(GND5) J7.B21(GND6) J7.B22(GND7) J7.B25(GND8) J7.B26(GND9) J7.B29(GND10) J7.B32(GND11) J7.B35(GND12) J7.B36(GND13) J7.B39(GND14) J7.B40(GND15) J7.B43(GND16) J7.B44(GND17) J7.B47(GND18) J7.B49(GND19) J7.B52(GND20) J7.B53(GND21) J7.B56(GND22) J7.B57(GND23) J7.B60(GND24) J7.B61(GND25) J7.B64(GND26) J7.B65(GND27) J7.B68(GND28) J7.B69(GND29) J7.B72(GND30) J7.B73(GND31) J7.B76(GND32) J7.B77(GND33) J7.B80(GND34) J8.A1(PRSNT1_N) J8.A4(GND35) J8.A12(GND36) J8.A15(GND37) J8.A18(GND38) J8.A20(GND39) J8.A23(GND40) J8.A24(GND41) J8.A27(GND42) J8.A28(GND43) J8.A31(GND44) J8.A34(GND45) J8.A37(GND46) J8.A38(GND47) J8.A41(GND48) J8.A42(GND49) J8.A45(GND50) J8.A46(GND51) J8.A49(GND52) J8.A51(GND53) J8.A54(GND54) J8.A55(GND55) J8.A58(GND56) J8.A59(GND57) J8.A62(GND58) J8.A63(GND59) J8.A66(GND60) J8.A67(RSVD8) J8.A70(GND61) J8.A71(GND62) J8.A74(GND63) J8.A75(GND64) J8.A78(GND65) J8.A79(GND66) J8.A82(GND67) J8.B4(GND1) J8.B7(GND2) J8.B13(GND3) J8.B16(GND4) J8.B18(GND5) J8.B21(GND6) J8.B22(GND7) J8.B25(GND8) J8.B26(GND9) J8.B29(GND10) J8.B32(GND11) J8.B35(GND12) J8.B36(GND13) J8.B39(GND14) J8.B40(GND15) J8.B43(GND16) J8.B44(GND17) J8.B47(GND18) J8.B49(GND19) J8.B52(GND20) J8.B53(GND21) J8.B56(GND22) J8.B57(GND23) J8.B60(GND24) J8.B61(GND25) J8.B64(GND26) J8.B65(GND27) J8.B68(GND28) J8.B69(GND29) J8.B72(GND30) J8.B73(GND31) J8.B76(GND32) J8.B77(GND33) J8.B80(GND34) J9.A1(PRSNT1_N) J9.A4(GND35) J9.A12(GND36) J9.A15(GND37) J9.A18(GND38) J9.A20(GND39) J9.A23(GND40) J9.A24(GND41) J9.A27(GND42) J9.A28(GND43) J9.A31(GND44) J9.A34(GND45) J9.A37(GND46) J9.A38(GND47) J9.A41(GND48) J9.A42(GND49) J9.A45(GND50) J9.A46(GND51) J9.A49(GND52) J9.A51(GND53) J9.A54(GND54) J9.A55(GND55) J9.A58(GND56) J9.A59(GND57) J9.A62(GND58) J9.A63(GND59) J9.A66(GND60) J9.A67(RSVD8) J9.A70(GND61) J9.A71(GND62) J9.A74(GND63) J9.A75(GND64) J9.A78(GND65) J9.A79(GND66) J9.A82(GND67) J9.B4(GND1) J9.B7(GND2) J9.B13(GND3) J9.B16(GND4) J9.B18(GND5) J9.B21(GND6) J9.B22(GND7) J9.B25(GND8) J9.B26(GND9) J9.B29(GND10) J9.B32(GND11) J9.B35(GND12) J9.B36(GND13) J9.B39(GND14) J9.B40(GND15) J9.B43(GND16) J9.B44(GND17) J9.B47(GND18) J9.B49(GND19) J9.B52(GND20) J9.B53(GND21) J9.B56(GND22) J9.B57(GND23) J9.B60(GND24) J9.B61(GND25) J9.B64(GND26) J9.B65(GND27) J9.B68(GND28) J9.B69(GND29) J9.B72(GND30) J9.B73(GND31) J9.B76(GND32) J9.B77(GND33) J9.B80(GND34) ; also on sheet 3 4 5 6 7 8 9 10 11 12 13 14 15 16 17 18 19 20 21 22 23 24 25 26 27 28 29 30 31 32 38 39 40 41 42 43 44 45 46 47 48 49 50 51 52 53 54 55 56 57 58 59 60 61 62 63 64 65 66 67
P3V3: C611.1 C612.1 C613.1 C655.1 C656.1 C657.1 C699.1 C700.1 C701.1 C743.1 C744.1 C745.1 C787.1 C788.1 C789.1 CE6.1 CE8.1 CE10.1 CE12.1 CE14.1 J5.A9(3.3V_2) J5.A10(3.3V_3) J5.B8(3.3V_1) J6.A9(3.3V_2) J6.A10(3.3V_3) J6.B8(3.3V_1) J7.A9(3.3V_2) J7.A10(3.3V_3) J7.B8(3.3V_1) J8.A9(3.3V_2) J8.A10(3.3V_3) J8.B8(3.3V_1) J9.A9(3.3V_2) J9.A10(3.3V_3) J9.B8(3.3V_1) ; also on sheet 10 22 27 28 31 32 38 41 44 51 53 59 60 61 62 63 64 65 66
P3V3_STBY: C609.1 C610.1 C653.1 C654.1 C691.1 C692.1 C741.1 C742.1 C779.1 C780.1 J5.B10(3.3VAUX) J6.B10(3.3VAUX) J7.B10(3.3VAUX) J8.B10(3.3VAUX) J9.B10(3.3VAUX) R529.1 R530.1 R531.1 R536.2 R537.1 R538.1 R539.1 R544.2 R545.1 R546.1 R547.1 R552.2 R553.1 R554.1 R555.1 R560.2 R561.1 R562.1 R563.1 R568.2 ; also on sheet 27 28 29 30 31 32 38 39 40 43 44 45 46 48 49 50 51 54 55 58 67
P12V: C647.1 C648.1 C649.1 C650.1 C651.1 C652.1 C693.1 C694.1 C695.1 C696.1 C697.1 C698.1 CE7.1 CE9.1 J6.A2(12V_4) J6.A3(12V_5) J6.B1(12V_1) J6.B2(12V_2) J6.B3(12V_3) J7.A2(12V_4) J7.A3(12V_5) J7.B1(12V_1) J7.B2(12V_2) J7.B3(12V_3) ; also on sheet 41 42 50 57 59 66
P12V_1: C603.1 C604.1 C605.1 C606.1 C607.1 C608.1 CE5.1 J5.A2(12V_4) J5.A3(12V_5) J5.B1(12V_1) J5.B2(12V_2) J5.B3(12V_3) ; also on sheet 31 32 42 48 52 60 62 64
P12V_2: C735.1 C736.1 C737.1 C738.1 C739.1 C740.1 C781.1 C782.1 C783.1 C784.1 C785.1 C786.1 CE11.1 CE13.1 J8.A2(12V_4) J8.A3(12V_5) J8.B1(12V_1) J8.B2(12V_2) J8.B3(12V_3) J9.A2(12V_4) J9.A3(12V_5) J9.B1(12V_1) J9.B2(12V_2) J9.B3(12V_3) ; also on sheet 38 42 49 52 61 63 65
CLK_100M_PE2_N: J5.A14(REFCLK-) ; also on sheet 27
CLK_100M_PE2_P: J5.A13(REFCLK+) ; also on sheet 27
CLK_100M_PE3_N: J6.A14(REFCLK-) ; also on sheet 27
CLK_100M_PE3_P: J6.A13(REFCLK+) ; also on sheet 27
CLK_100M_PE4_N: J7.A14(REFCLK-) ; also on sheet 28
CLK_100M_PE4_P: J7.A13(REFCLK+) ; also on sheet 28
CLK_100M_PE5_N: J8.A14(REFCLK-) ; also on sheet 28
CLK_100M_PE5_P: J8.A13(REFCLK+) ; also on sheet 28
CLK_100M_PE6_N: J9.A14(REFCLK-) ; also on sheet 28
CLK_100M_PE6_P: J9.A13(REFCLK+) ; also on sheet 28
GPU_THROTTLE_SLOT2_N: R535.1 ; also on sheet 67
GPU_THROTTLE_SLOT2_R_N: J5.B12(RSVD1) R531.2 R535.2
GPU_THROTTLE_SLOT3_N: R543.1 ; also on sheet 67
GPU_THROTTLE_SLOT3_R_N: J6.B12(RSVD1) R539.2 R543.2
GPU_THROTTLE_SLOT4_N: R550.1 ; also on sheet 67
GPU_THROTTLE_SLOT4_R_N: J7.B12(RSVD1) R547.2 R550.2
GPU_THROTTLE_SLOT5_N: R559.1 ; also on sheet 67
GPU_THROTTLE_SLOT5_R_N: J8.B12(RSVD1) R555.2 R559.2
GPU_THROTTLE_SLOT6_N: R567.1 ; also on sheet 67
GPU_THROTTLE_SLOT6_R_N: J9.B12(RSVD1) R563.2 R567.2
PE_SLOT2_PRSNT_N: C646.1 J5.B17(PRSNT2_N-1) J5.B31(PRSNT2_N-2) J5.B48(PRSNT2_N-3) J5.B81(PRSNT2_N-4) R536.1 ; also on sheet 27
PE_SLOT3_PRSNT_N: C690.1 J6.B17(PRSNT2_N-1) J6.B31(PRSNT2_N-2) J6.B48(PRSNT2_N-3) J6.B81(PRSNT2_N-4) R544.1 ; also on sheet 27
PE_SLOT4_PRSNT_N: C734.1 J7.B17(PRSNT2_N-1) J7.B31(PRSNT2_N-2) J7.B48(PRSNT2_N-3) J7.B81(PRSNT2_N-4) R552.1 ; also on sheet 28
PE_SLOT5_PRSNT_N: C778.1 J8.B17(PRSNT2_N-1) J8.B31(PRSNT2_N-2) J8.B48(PRSNT2_N-3) J8.B81(PRSNT2_N-4) R560.1 ; also on sheet 28
PE_SLOT6_PRSNT_N: C822.1 J9.B17(PRSNT2_N-1) J9.B31(PRSNT2_N-2) J9.B48(PRSNT2_N-3) J9.B81(PRSNT2_N-4) R568.1 ; also on sheet 28
PEX_PE2_RXN0: J5.A17(HSIP0-) ; also on sheet 8
PEX_PE2_RXN1: J5.A22(HSIP1-) ; also on sheet 8
PEX_PE2_RXN2: J5.A26(HSIP2-) ; also on sheet 8
PEX_PE2_RXN3: J5.A30(HSIP3-) ; also on sheet 8
PEX_PE2_RXN4: J5.A36(HSIP4-) ; also on sheet 8
PEX_PE2_RXN5: J5.A40(HSIP5-) ; also on sheet 8
PEX_PE2_RXN6: J5.A44(HSIP6-) ; also on sheet 8
PEX_PE2_RXN7: J5.A48(HSIP7-) ; also on sheet 8
PEX_PE2_RXN8: J5.A53(HSIP8-) ; also on sheet 8
PEX_PE2_RXN9: J5.A57(HSIP9-) ; also on sheet 8
PEX_PE2_RXN10: J5.A61(HSIP10-) ; also on sheet 8
PEX_PE2_RXN11: J5.A65(HSIP11-) ; also on sheet 8
PEX_PE2_RXN12: J5.A69(HSIP12-) ; also on sheet 8
PEX_PE2_RXN13: J5.A73(HSIP13-) ; also on sheet 8
PEX_PE2_RXN14: J5.A77(HSIP14-) ; also on sheet 8
PEX_PE2_RXN15: J5.A81(HSIP15-) ; also on sheet 8
PEX_PE2_RXP0: J5.A16(HSIP0+) ; also on sheet 8
PEX_PE2_RXP1: J5.A21(HSIP1+) ; also on sheet 8
PEX_PE2_RXP2: J5.A25(HSIP2+) ; also on sheet 8
PEX_PE2_RXP3: J5.A29(HSIP3+) ; also on sheet 8
PEX_PE2_RXP4: J5.A35(HSIP4+) ; also on sheet 8
PEX_PE2_RXP5: J5.A39(HSIP5+) ; also on sheet 8
PEX_PE2_RXP6: J5.A43(HSIP6+) ; also on sheet 8
PEX_PE2_RXP7: J5.A47(HSIP7+) ; also on sheet 8
PEX_PE2_RXP8: J5.A52(HSIP8+) ; also on sheet 8
PEX_PE2_RXP9: J5.A56(HSIP9+) ; also on sheet 8
PEX_PE2_RXP10: J5.A60(HSIP10+) ; also on sheet 8
PEX_PE2_RXP11: J5.A64(HSIP11+) ; also on sheet 8
PEX_PE2_RXP12: J5.A68(HSIP12+) ; also on sheet 8
PEX_PE2_RXP13: J5.A72(HSIP13+) ; also on sheet 8
PEX_PE2_RXP14: J5.A76(HSIP14) ; also on sheet 8
PEX_PE2_RXP15: J5.A80(HSIP15+) ; also on sheet 8
PEX_PE2_TXN0: C615.1 ; also on sheet 8
PEX_PE2_TXN0_C: C615.2 J5.B15(HSOP0-)
PEX_PE2_TXN1: C617.1 ; also on sheet 8
PEX_PE2_TXN1_C: C617.2 J5.B20(HSOP1-)
PEX_PE2_TXN2: C619.1 ; also on sheet 8
PEX_PE2_TXN2_C: C619.2 J5.B24(HSOP2-)
PEX_PE2_TXN3: C621.1 ; also on sheet 8
PEX_PE2_TXN3_C: C621.2 J5.B28(HSOP3-)
PEX_PE2_TXN4: C623.1 ; also on sheet 8
PEX_PE2_TXN4_C: C623.2 J5.B34(HSOP4-)
PEX_PE2_TXN5: C625.1 ; also on sheet 8
PEX_PE2_TXN5_C: C625.2 J5.B38(HSOP5-)
PEX_PE2_TXN6: C627.1 ; also on sheet 8
PEX_PE2_TXN6_C: C627.2 J5.B42(HSOP6-)
PEX_PE2_TXN7: C629.1 ; also on sheet 8
PEX_PE2_TXN7_C: C629.2 J5.B46(HSOP7-)
PEX_PE2_TXN8: C631.1 ; also on sheet 8
PEX_PE2_TXN8_C: C631.2 J5.B51(HSOP8-)
PEX_PE2_TXN9: C633.1 ; also on sheet 8
PEX_PE2_TXN9_C: C633.2 J5.B55(HSOP9-)
PEX_PE2_TXN10: C635.1 ; also on sheet 8
PEX_PE2_TXN10_C: C635.2 J5.B59(HSOP10-)
PEX_PE2_TXN11: C637.1 ; also on sheet 8
PEX_PE2_TXN11_C: C637.2 J5.B63(HSOP11-)
PEX_PE2_TXN12: C639.1 ; also on sheet 8
PEX_PE2_TXN12_C: C639.2 J5.B67(HSOP12-)
PEX_PE2_TXN13: C641.1 ; also on sheet 8
PEX_PE2_TXN13_C: C641.2 J5.B71(HSOP13-)
PEX_PE2_TXN14: C643.1 ; also on sheet 8
PEX_PE2_TXN14_C: C643.2 J5.B75(HSOP14-)
PEX_PE2_TXN15: C645.1 ; also on sheet 8
PEX_PE2_TXN15_C: C645.2 J5.B79(HSOP15-)
PEX_PE2_TXP0: C614.1 ; also on sheet 8
PEX_PE2_TXP0_C: C614.2 J5.B14(HSOP0+)
PEX_PE2_TXP1: C616.1 ; also on sheet 8
PEX_PE2_TXP1_C: C616.2 J5.B19(HSOP1+)
PEX_PE2_TXP2: C618.1 ; also on sheet 8
PEX_PE2_TXP2_C: C618.2 J5.B23(HSOP2+)
PEX_PE2_TXP3: C620.1 ; also on sheet 8
PEX_PE2_TXP3_C: C620.2 J5.B27(HSOP3+)
PEX_PE2_TXP4: C622.1 ; also on sheet 8
PEX_PE2_TXP4_C: C622.2 J5.B33(HSOP4+)
PEX_PE2_TXP5: C624.1 ; also on sheet 8
PEX_PE2_TXP5_C: C624.2 J5.B37(HSOP5+)
PEX_PE2_TXP6: C626.1 ; also on sheet 8
PEX_PE2_TXP6_C: C626.2 J5.B41(HSOP6+)
PEX_PE2_TXP7: C628.1 ; also on sheet 8
PEX_PE2_TXP7_C: C628.2 J5.B45(HSOP7+)
PEX_PE2_TXP8: C630.1 ; also on sheet 8
PEX_PE2_TXP8_C: C630.2 J5.B50(HSOP8+)
PEX_PE2_TXP9: C632.1 ; also on sheet 8
PEX_PE2_TXP9_C: C632.2 J5.B54(HSOP9+)
PEX_PE2_TXP10: C634.1 ; also on sheet 8
PEX_PE2_TXP10_C: C634.2 J5.B58(HSOP10+)
PEX_PE2_TXP11: C636.1 ; also on sheet 8
PEX_PE2_TXP11_C: C636.2 J5.B62(HSOP11+)
PEX_PE2_TXP12: C638.1 ; also on sheet 8
PEX_PE2_TXP12_C: C638.2 J5.B66(HSOP12+)
PEX_PE2_TXP13: C640.1 ; also on sheet 8
PEX_PE2_TXP13_C: C640.2 J5.B70(HSOP13+)
PEX_PE2_TXP14: C642.1 ; also on sheet 8
PEX_PE2_TXP14_C: C642.2 J5.B74(HSOP14+)
PEX_PE2_TXP15: C644.1 ; also on sheet 8
PEX_PE2_TXP15_C: C644.2 J5.B78(HSOP15+)
PEX_PE3_RXN0: J6.A17(HSIP0-) ; also on sheet 6
PEX_PE3_RXN1: J6.A22(HSIP1-) ; also on sheet 6
PEX_PE3_RXN2: J6.A26(HSIP2-) ; also on sheet 6
PEX_PE3_RXN3: J6.A30(HSIP3-) ; also on sheet 6
PEX_PE3_RXN4: J6.A36(HSIP4-) ; also on sheet 6
PEX_PE3_RXN5: J6.A40(HSIP5-) ; also on sheet 6
PEX_PE3_RXN6: J6.A44(HSIP6-) ; also on sheet 6
PEX_PE3_RXN7: J6.A48(HSIP7-) ; also on sheet 6
PEX_PE3_RXN8: J6.A53(HSIP8-) ; also on sheet 6
PEX_PE3_RXN9: J6.A57(HSIP9-) ; also on sheet 6
PEX_PE3_RXN10: J6.A61(HSIP10-) ; also on sheet 6
PEX_PE3_RXN11: J6.A65(HSIP11-) ; also on sheet 6
PEX_PE3_RXN12: J6.A69(HSIP12-) ; also on sheet 6
PEX_PE3_RXN13: J6.A73(HSIP13-) ; also on sheet 6
PEX_PE3_RXN14: J6.A77(HSIP14-) ; also on sheet 6
PEX_PE3_RXN15: J6.A81(HSIP15-) ; also on sheet 6
PEX_PE3_RXP0: J6.A16(HSIP0+) ; also on sheet 6
PEX_PE3_RXP1: J6.A21(HSIP1+) ; also on sheet 6
PEX_PE3_RXP2: J6.A25(HSIP2+) ; also on sheet 6
PEX_PE3_RXP3: J6.A29(HSIP3+) ; also on sheet 6
PEX_PE3_RXP4: J6.A35(HSIP4+) ; also on sheet 6
PEX_PE3_RXP5: J6.A39(HSIP5+) ; also on sheet 6
PEX_PE3_RXP6: J6.A43(HSIP6+) ; also on sheet 6
PEX_PE3_RXP7: J6.A47(HSIP7+) ; also on sheet 6
PEX_PE3_RXP8: J6.A52(HSIP8+) ; also on sheet 6
PEX_PE3_RXP9: J6.A56(HSIP9+) ; also on sheet 6
PEX_PE3_RXP10: J6.A60(HSIP10+) ; also on sheet 6
PEX_PE3_RXP11: J6.A64(HSIP11+) ; also on sheet 6
PEX_PE3_RXP12: J6.A68(HSIP12+) ; also on sheet 6
PEX_PE3_RXP13: J6.A72(HSIP13+) ; also on sheet 6
PEX_PE3_RXP14: J6.A76(HSIP14) ; also on sheet 6
PEX_PE3_RXP15: J6.A80(HSIP15+) ; also on sheet 6
PEX_PE3_TXN0: C659.1 ; also on sheet 6
PEX_PE3_TXN0_C: C659.2 J6.B15(HSOP0-)
PEX_PE3_TXN1: C661.1 ; also on sheet 6
PEX_PE3_TXN1_C: C661.2 J6.B20(HSOP1-)
PEX_PE3_TXN2: C663.1 ; also on sheet 6
PEX_PE3_TXN2_C: C663.2 J6.B24(HSOP2-)
PEX_PE3_TXN3: C665.1 ; also on sheet 6
PEX_PE3_TXN3_C: C665.2 J6.B28(HSOP3-)
PEX_PE3_TXN4: C667.1 ; also on sheet 6
PEX_PE3_TXN4_C: C667.2 J6.B34(HSOP4-)
PEX_PE3_TXN5: C669.1 ; also on sheet 6
PEX_PE3_TXN5_C: C669.2 J6.B38(HSOP5-)
PEX_PE3_TXN6: C671.1 ; also on sheet 6
PEX_PE3_TXN6_C: C671.2 J6.B42(HSOP6-)
PEX_PE3_TXN7: C673.1 ; also on sheet 6
PEX_PE3_TXN7_C: C673.2 J6.B46(HSOP7-)
PEX_PE3_TXN8: C675.1 ; also on sheet 6
PEX_PE3_TXN8_C: C675.2 J6.B51(HSOP8-)
PEX_PE3_TXN9: C677.1 ; also on sheet 6
PEX_PE3_TXN9_C: C677.2 J6.B55(HSOP9-)
PEX_PE3_TXN10: C679.1 ; also on sheet 6
PEX_PE3_TXN10_C: C679.2 J6.B59(HSOP10-)
PEX_PE3_TXN11: C681.1 ; also on sheet 6
PEX_PE3_TXN11_C: C681.2 J6.B63(HSOP11-)
PEX_PE3_TXN12: C683.1 ; also on sheet 6
PEX_PE3_TXN12_C: C683.2 J6.B67(HSOP12-)
PEX_PE3_TXN13: C685.1 ; also on sheet 6
PEX_PE3_TXN13_C: C685.2 J6.B71(HSOP13-)
PEX_PE3_TXN14: C687.1 ; also on sheet 6
PEX_PE3_TXN14_C: C687.2 J6.B75(HSOP14-)
PEX_PE3_TXN15: C689.1 ; also on sheet 6
PEX_PE3_TXN15_C: C689.2 J6.B79(HSOP15-)
PEX_PE3_TXP0: C658.1 ; also on sheet 6
PEX_PE3_TXP0_C: C658.2 J6.B14(HSOP0+)
PEX_PE3_TXP1: C660.1 ; also on sheet 6
PEX_PE3_TXP1_C: C660.2 J6.B19(HSOP1+)
PEX_PE3_TXP2: C662.1 ; also on sheet 6
PEX_PE3_TXP2_C: C662.2 J6.B23(HSOP2+)
PEX_PE3_TXP3: C664.1 ; also on sheet 6
PEX_PE3_TXP3_C: C664.2 J6.B27(HSOP3+)
PEX_PE3_TXP4: C666.1 ; also on sheet 6
PEX_PE3_TXP4_C: C666.2 J6.B33(HSOP4+)
PEX_PE3_TXP5: C668.1 ; also on sheet 6
PEX_PE3_TXP5_C: C668.2 J6.B37(HSOP5+)
PEX_PE3_TXP6: C670.1 ; also on sheet 6
PEX_PE3_TXP6_C: C670.2 J6.B41(HSOP6+)
PEX_PE3_TXP7: C672.1 ; also on sheet 6
PEX_PE3_TXP7_C: C672.2 J6.B45(HSOP7+)
PEX_PE3_TXP8: C674.1 ; also on sheet 6
PEX_PE3_TXP8_C: C674.2 J6.B50(HSOP8+)
PEX_PE3_TXP9: C676.1 ; also on sheet 6
PEX_PE3_TXP9_C: C676.2 J6.B54(HSOP9+)
PEX_PE3_TXP10: C678.1 ; also on sheet 6
PEX_PE3_TXP10_C: C678.2 J6.B58(HSOP10+)
PEX_PE3_TXP11: C680.1 ; also on sheet 6
PEX_PE3_TXP11_C: C680.2 J6.B62(HSOP11+)
PEX_PE3_TXP12: C682.1 ; also on sheet 6
PEX_PE3_TXP12_C: C682.2 J6.B66(HSOP12+)
PEX_PE3_TXP13: C684.1 ; also on sheet 6
PEX_PE3_TXP13_C: C684.2 J6.B70(HSOP13+)
PEX_PE3_TXP14: C686.1 ; also on sheet 6
PEX_PE3_TXP14_C: C686.2 J6.B74(HSOP14+)
PEX_PE3_TXP15: C688.1 ; also on sheet 6
PEX_PE3_TXP15_C: C688.2 J6.B78(HSOP15+)
PEX_PE4_RXN0: J7.A17(HSIP0-) ; also on sheet 17
PEX_PE4_RXN1: J7.A22(HSIP1-) ; also on sheet 17
PEX_PE4_RXN2: J7.A26(HSIP2-) ; also on sheet 17
PEX_PE4_RXN3: J7.A30(HSIP3-) ; also on sheet 17
PEX_PE4_RXN4: J7.A36(HSIP4-) ; also on sheet 17
PEX_PE4_RXN5: J7.A40(HSIP5-) ; also on sheet 17
PEX_PE4_RXN6: J7.A44(HSIP6-) ; also on sheet 17
PEX_PE4_RXN7: J7.A48(HSIP7-) ; also on sheet 17
PEX_PE4_RXN8: J7.A53(HSIP8-) ; also on sheet 17
PEX_PE4_RXN9: J7.A57(HSIP9-) ; also on sheet 17
PEX_PE4_RXN10: J7.A61(HSIP10-) ; also on sheet 17
PEX_PE4_RXN11: J7.A65(HSIP11-) ; also on sheet 17
PEX_PE4_RXN12: J7.A69(HSIP12-) ; also on sheet 17
PEX_PE4_RXN13: J7.A73(HSIP13-) ; also on sheet 17
PEX_PE4_RXN14: J7.A77(HSIP14-) ; also on sheet 17
PEX_PE4_RXN15: J7.A81(HSIP15-) ; also on sheet 17
PEX_PE4_RXP0: J7.A16(HSIP0+) ; also on sheet 17
PEX_PE4_RXP1: J7.A21(HSIP1+) ; also on sheet 17
PEX_PE4_RXP2: J7.A25(HSIP2+) ; also on sheet 17
PEX_PE4_RXP3: J7.A29(HSIP3+) ; also on sheet 17
PEX_PE4_RXP4: J7.A35(HSIP4+) ; also on sheet 17
PEX_PE4_RXP5: J7.A39(HSIP5+) ; also on sheet 17
PEX_PE4_RXP6: J7.A43(HSIP6+) ; also on sheet 17
PEX_PE4_RXP7: J7.A47(HSIP7+) ; also on sheet 17
PEX_PE4_RXP8: J7.A52(HSIP8+) ; also on sheet 17
PEX_PE4_RXP9: J7.A56(HSIP9+) ; also on sheet 17
PEX_PE4_RXP10: J7.A60(HSIP10+) ; also on sheet 17
PEX_PE4_RXP11: J7.A64(HSIP11+) ; also on sheet 17
PEX_PE4_RXP12: J7.A68(HSIP12+) ; also on sheet 17
PEX_PE4_RXP13: J7.A72(HSIP13+) ; also on sheet 17
PEX_PE4_RXP14: J7.A76(HSIP14) ; also on sheet 17
PEX_PE4_RXP15: J7.A80(HSIP15+) ; also on sheet 17
PEX_PE4_TXN0: C703.1 ; also on sheet 17
PEX_PE4_TXN0_C: C703.2 J7.B15(HSOP0-)
PEX_PE4_TXN1: C705.1 ; also on sheet 17
PEX_PE4_TXN1_C: C705.2 J7.B20(HSOP1-)
PEX_PE4_TXN2: C707.1 ; also on sheet 17
PEX_PE4_TXN2_C: C707.2 J7.B24(HSOP2-)
PEX_PE4_TXN3: C709.1 ; also on sheet 17
PEX_PE4_TXN3_C: C709.2 J7.B28(HSOP3-)
PEX_PE4_TXN4: C711.1 ; also on sheet 17
PEX_PE4_TXN4_C: C711.2 J7.B34(HSOP4-)
PEX_PE4_TXN5: C713.1 ; also on sheet 17
PEX_PE4_TXN5_C: C713.2 J7.B38(HSOP5-)
PEX_PE4_TXN6: C715.1 ; also on sheet 17
PEX_PE4_TXN6_C: C715.2 J7.B42(HSOP6-)
PEX_PE4_TXN7: C717.1 ; also on sheet 17
PEX_PE4_TXN7_C: C717.2 J7.B46(HSOP7-)
PEX_PE4_TXN8: C719.1 ; also on sheet 17
PEX_PE4_TXN8_C: C719.2 J7.B51(HSOP8-)
PEX_PE4_TXN9: C721.1 ; also on sheet 17
PEX_PE4_TXN9_C: C721.2 J7.B55(HSOP9-)
PEX_PE4_TXN10: C723.1 ; also on sheet 17
PEX_PE4_TXN10_C: C723.2 J7.B59(HSOP10-)
PEX_PE4_TXN11: C725.1 ; also on sheet 17
PEX_PE4_TXN11_C: C725.2 J7.B63(HSOP11-)
PEX_PE4_TXN12: C727.1 ; also on sheet 17
PEX_PE4_TXN12_C: C727.2 J7.B67(HSOP12-)
PEX_PE4_TXN13: C729.1 ; also on sheet 17
PEX_PE4_TXN13_C: C729.2 J7.B71(HSOP13-)
PEX_PE4_TXN14: C731.1 ; also on sheet 17
PEX_PE4_TXN14_C: C731.2 J7.B75(HSOP14-)
PEX_PE4_TXN15: C733.1 ; also on sheet 17
PEX_PE4_TXN15_C: C733.2 J7.B79(HSOP15-)
PEX_PE4_TXP0: C702.1 ; also on sheet 17
PEX_PE4_TXP0_C: C702.2 J7.B14(HSOP0+)
PEX_PE4_TXP1: C704.1 ; also on sheet 17
PEX_PE4_TXP1_C: C704.2 J7.B19(HSOP1+)
PEX_PE4_TXP2: C706.1 ; also on sheet 17
PEX_PE4_TXP2_C: C706.2 J7.B23(HSOP2+)
PEX_PE4_TXP3: C708.1 ; also on sheet 17
PEX_PE4_TXP3_C: C708.2 J7.B27(HSOP3+)
PEX_PE4_TXP4: C710.1 ; also on sheet 17
PEX_PE4_TXP4_C: C710.2 J7.B33(HSOP4+)
PEX_PE4_TXP5: C712.1 ; also on sheet 17
PEX_PE4_TXP5_C: C712.2 J7.B37(HSOP5+)
PEX_PE4_TXP6: C714.1 ; also on sheet 17
PEX_PE4_TXP6_C: C714.2 J7.B41(HSOP6+)
PEX_PE4_TXP7: C716.1 ; also on sheet 17
PEX_PE4_TXP7_C: C716.2 J7.B45(HSOP7+)
PEX_PE4_TXP8: C718.1 ; also on sheet 17
PEX_PE4_TXP8_C: C718.2 J7.B50(HSOP8+)
PEX_PE4_TXP9: C720.1 ; also on sheet 17
PEX_PE4_TXP9_C: C720.2 J7.B54(HSOP9+)
PEX_PE4_TXP10: C722.1 ; also on sheet 17
PEX_PE4_TXP10_C: C722.2 J7.B58(HSOP10+)
PEX_PE4_TXP11: C724.1 ; also on sheet 17
PEX_PE4_TXP11_C: C724.2 J7.B62(HSOP11+)
PEX_PE4_TXP12: C726.1 ; also on sheet 17
PEX_PE4_TXP12_C: C726.2 J7.B66(HSOP12+)
PEX_PE4_TXP13: C728.1 ; also on sheet 17
PEX_PE4_TXP13_C: C728.2 J7.B70(HSOP13+)
PEX_PE4_TXP14: C730.1 ; also on sheet 17
PEX_PE4_TXP14_C: C730.2 J7.B74(HSOP14+)
PEX_PE4_TXP15: C732.1 ; also on sheet 17
PEX_PE4_TXP15_C: C732.2 J7.B78(HSOP15+)
PEX_PE5_RXN0: J8.A17(HSIP0-) ; also on sheet 19
PEX_PE5_RXN1: J8.A22(HSIP1-) ; also on sheet 19
PEX_PE5_RXN2: J8.A26(HSIP2-) ; also on sheet 19
PEX_PE5_RXN3: J8.A30(HSIP3-) ; also on sheet 19
PEX_PE5_RXN4: J8.A36(HSIP4-) ; also on sheet 19
PEX_PE5_RXN5: J8.A40(HSIP5-) ; also on sheet 19
PEX_PE5_RXN6: J8.A44(HSIP6-) ; also on sheet 19
PEX_PE5_RXN7: J8.A48(HSIP7-) ; also on sheet 19
PEX_PE5_RXN8: J8.A53(HSIP8-) ; also on sheet 19
PEX_PE5_RXN9: J8.A57(HSIP9-) ; also on sheet 19
PEX_PE5_RXN10: J8.A61(HSIP10-) ; also on sheet 19
PEX_PE5_RXN11: J8.A65(HSIP11-) ; also on sheet 19
PEX_PE5_RXN12: J8.A69(HSIP12-) ; also on sheet 19
PEX_PE5_RXN13: J8.A73(HSIP13-) ; also on sheet 19
PEX_PE5_RXN14: J8.A77(HSIP14-) ; also on sheet 19
PEX_PE5_RXN15: J8.A81(HSIP15-) ; also on sheet 19
PEX_PE5_RXP0: J8.A16(HSIP0+) ; also on sheet 19
PEX_PE5_RXP1: J8.A21(HSIP1+) ; also on sheet 19
PEX_PE5_RXP2: J8.A25(HSIP2+) ; also on sheet 19
PEX_PE5_RXP3: J8.A29(HSIP3+) ; also on sheet 19
PEX_PE5_RXP4: J8.A35(HSIP4+) ; also on sheet 19
PEX_PE5_RXP5: J8.A39(HSIP5+) ; also on sheet 19
PEX_PE5_RXP6: J8.A43(HSIP6+) ; also on sheet 19
PEX_PE5_RXP7: J8.A47(HSIP7+) ; also on sheet 19
PEX_PE5_RXP8: J8.A52(HSIP8+) ; also on sheet 19
PEX_PE5_RXP9: J8.A56(HSIP9+) ; also on sheet 19
PEX_PE5_RXP10: J8.A60(HSIP10+) ; also on sheet 19
PEX_PE5_RXP11: J8.A64(HSIP11+) ; also on sheet 19
PEX_PE5_RXP12: J8.A68(HSIP12+) ; also on sheet 19
PEX_PE5_RXP13: J8.A72(HSIP13+) ; also on sheet 19
PEX_PE5_RXP14: J8.A76(HSIP14) ; also on sheet 19
PEX_PE5_RXP15: J8.A80(HSIP15+) ; also on sheet 19
PEX_PE5_TXN0: C746.1 ; also on sheet 19
PEX_PE5_TXN0_C: C746.2 J8.B15(HSOP0-)
PEX_PE5_TXN1: C749.1 ; also on sheet 19
PEX_PE5_TXN1_C: C749.2 J8.B20(HSOP1-)
PEX_PE5_TXN2: C751.1 ; also on sheet 19
PEX_PE5_TXN2_C: C751.2 J8.B24(HSOP2-)
PEX_PE5_TXN3: C753.1 ; also on sheet 19
PEX_PE5_TXN3_C: C753.2 J8.B28(HSOP3-)
PEX_PE5_TXN4: C755.1 ; also on sheet 19
PEX_PE5_TXN4_C: C755.2 J8.B34(HSOP4-)
PEX_PE5_TXN5: C757.1 ; also on sheet 19
PEX_PE5_TXN5_C: C757.2 J8.B38(HSOP5-)
PEX_PE5_TXN6: C759.1 ; also on sheet 19
PEX_PE5_TXN6_C: C759.2 J8.B42(HSOP6-)
PEX_PE5_TXN7: C761.1 ; also on sheet 19
PEX_PE5_TXN7_C: C761.2 J8.B46(HSOP7-)
PEX_PE5_TXN8: C763.1 ; also on sheet 19
PEX_PE5_TXN8_C: C763.2 J8.B51(HSOP8-)
PEX_PE5_TXN9: C765.1 ; also on sheet 19
PEX_PE5_TXN9_C: C765.2 J8.B55(HSOP9-)
PEX_PE5_TXN10: C767.1 ; also on sheet 19
PEX_PE5_TXN10_C: C767.2 J8.B59(HSOP10-)
PEX_PE5_TXN11: C769.1 ; also on sheet 19
PEX_PE5_TXN11_C: C769.2 J8.B63(HSOP11-)
PEX_PE5_TXN12: C771.1 ; also on sheet 19
PEX_PE5_TXN12_C: C771.2 J8.B67(HSOP12-)
PEX_PE5_TXN13: C773.1 ; also on sheet 19
PEX_PE5_TXN13_C: C773.2 J8.B71(HSOP13-)
PEX_PE5_TXN14: C775.1 ; also on sheet 19
PEX_PE5_TXN14_C: C775.2 J8.B75(HSOP14-)
PEX_PE5_TXN15: C777.1 ; also on sheet 19
PEX_PE5_TXN15_C: C777.2 J8.B79(HSOP15-)
PEX_PE5_TXP0: C747.1 ; also on sheet 19
PEX_PE5_TXP0_C: C747.2 J8.B14(HSOP0+)
PEX_PE5_TXP1: C748.1 ; also on sheet 19
PEX_PE5_TXP1_C: C748.2 J8.B19(HSOP1+)
PEX_PE5_TXP2: C750.1 ; also on sheet 19
PEX_PE5_TXP2_C: C750.2 J8.B23(HSOP2+)
PEX_PE5_TXP3: C752.1 ; also on sheet 19
PEX_PE5_TXP3_C: C752.2 J8.B27(HSOP3+)
PEX_PE5_TXP4: C754.1 ; also on sheet 19
PEX_PE5_TXP4_C: C754.2 J8.B33(HSOP4+)
PEX_PE5_TXP5: C756.1 ; also on sheet 19
PEX_PE5_TXP5_C: C756.2 J8.B37(HSOP5+)
PEX_PE5_TXP6: C758.1 ; also on sheet 19
PEX_PE5_TXP6_C: C758.2 J8.B41(HSOP6+)
PEX_PE5_TXP7: C760.1 ; also on sheet 19
PEX_PE5_TXP7_C: C760.2 J8.B45(HSOP7+)
PEX_PE5_TXP8: C762.1 ; also on sheet 19
PEX_PE5_TXP8_C: C762.2 J8.B50(HSOP8+)
PEX_PE5_TXP9: C764.1 ; also on sheet 19
PEX_PE5_TXP9_C: C764.2 J8.B54(HSOP9+)
PEX_PE5_TXP10: C766.1 ; also on sheet 19
PEX_PE5_TXP10_C: C766.2 J8.B58(HSOP10+)
PEX_PE5_TXP11: C768.1 ; also on sheet 19
PEX_PE5_TXP11_C: C768.2 J8.B62(HSOP11+)
PEX_PE5_TXP12: C770.1 ; also on sheet 19
PEX_PE5_TXP12_C: C770.2 J8.B66(HSOP12+)
PEX_PE5_TXP13: C772.1 ; also on sheet 19
PEX_PE5_TXP13_C: C772.2 J8.B70(HSOP13+)
PEX_PE5_TXP14: C774.1 ; also on sheet 19
PEX_PE5_TXP14_C: C774.2 J8.B74(HSOP14+)
PEX_PE5_TXP15: C776.1 ; also on sheet 19
PEX_PE5_TXP15_C: C776.2 J8.B78(HSOP15+)
PEX_PE6_RXN0: J9.A17(HSIP0-) ; also on sheet 20
PEX_PE6_RXN1: J9.A22(HSIP1-) ; also on sheet 20
PEX_PE6_RXN2: J9.A26(HSIP2-) ; also on sheet 20
PEX_PE6_RXN3: J9.A30(HSIP3-) ; also on sheet 20
PEX_PE6_RXN4: J9.A36(HSIP4-) ; also on sheet 20
PEX_PE6_RXN5: J9.A40(HSIP5-) ; also on sheet 20
PEX_PE6_RXN6: J9.A44(HSIP6-) ; also on sheet 20
PEX_PE6_RXN7: J9.A48(HSIP7-) ; also on sheet 20
PEX_PE6_RXN8: J9.A53(HSIP8-) ; also on sheet 20
PEX_PE6_RXN9: J9.A57(HSIP9-) ; also on sheet 20
PEX_PE6_RXN10: J9.A61(HSIP10-) ; also on sheet 20
PEX_PE6_RXN11: J9.A65(HSIP11-) ; also on sheet 20
PEX_PE6_RXN12: J9.A69(HSIP12-) ; also on sheet 20
PEX_PE6_RXN13: J9.A73(HSIP13-) ; also on sheet 20
PEX_PE6_RXN14: J9.A77(HSIP14-) ; also on sheet 20
PEX_PE6_RXN15: J9.A81(HSIP15-) ; also on sheet 20
PEX_PE6_RXP0: J9.A16(HSIP0+) ; also on sheet 20
PEX_PE6_RXP1: J9.A21(HSIP1+) ; also on sheet 20
PEX_PE6_RXP2: J9.A25(HSIP2+) ; also on sheet 20
PEX_PE6_RXP3: J9.A29(HSIP3+) ; also on sheet 20
PEX_PE6_RXP4: J9.A35(HSIP4+) ; also on sheet 20
PEX_PE6_RXP5: J9.A39(HSIP5+) ; also on sheet 20
PEX_PE6_RXP6: J9.A43(HSIP6+) ; also on sheet 20
PEX_PE6_RXP7: J9.A47(HSIP7+) ; also on sheet 20
PEX_PE6_RXP8: J9.A52(HSIP8+) ; also on sheet 20
PEX_PE6_RXP9: J9.A56(HSIP9+) ; also on sheet 20
PEX_PE6_RXP10: J9.A60(HSIP10+) ; also on sheet 20
PEX_PE6_RXP11: J9.A64(HSIP11+) ; also on sheet 20
PEX_PE6_RXP12: J9.A68(HSIP12+) ; also on sheet 20
PEX_PE6_RXP13: J9.A72(HSIP13+) ; also on sheet 20
PEX_PE6_RXP14: J9.A76(HSIP14) ; also on sheet 20
PEX_PE6_RXP15: J9.A80(HSIP15+) ; also on sheet 20
PEX_PE6_TXN0: C791.1 ; also on sheet 20
PEX_PE6_TXN0_C: C791.2 J9.B15(HSOP0-)
PEX_PE6_TXN1: C793.1 ; also on sheet 20
PEX_PE6_TXN1_C: C793.2 J9.B20(HSOP1-)
PEX_PE6_TXN2: C795.1 ; also on sheet 20
PEX_PE6_TXN2_C: C795.2 J9.B24(HSOP2-)
PEX_PE6_TXN3: C797.1 ; also on sheet 20
PEX_PE6_TXN3_C: C797.2 J9.B28(HSOP3-)
PEX_PE6_TXN4: C799.1 ; also on sheet 20
PEX_PE6_TXN4_C: C799.2 J9.B34(HSOP4-)
PEX_PE6_TXN5: C801.1 ; also on sheet 20
PEX_PE6_TXN5_C: C801.2 J9.B38(HSOP5-)
PEX_PE6_TXN6: C803.1 ; also on sheet 20
PEX_PE6_TXN6_C: C803.2 J9.B42(HSOP6-)
PEX_PE6_TXN7: C805.1 ; also on sheet 20
PEX_PE6_TXN7_C: C805.2 J9.B46(HSOP7-)
PEX_PE6_TXN8: C807.1 ; also on sheet 20
PEX_PE6_TXN8_C: C807.2 J9.B51(HSOP8-)
PEX_PE6_TXN9: C809.1 ; also on sheet 20
PEX_PE6_TXN9_C: C809.2 J9.B55(HSOP9-)
PEX_PE6_TXN10: C811.1 ; also on sheet 20
PEX_PE6_TXN10_C: C811.2 J9.B59(HSOP10-)
PEX_PE6_TXN11: C813.1 ; also on sheet 20
PEX_PE6_TXN11_C: C813.2 J9.B63(HSOP11-)
PEX_PE6_TXN12: C815.1 ; also on sheet 20
PEX_PE6_TXN12_C: C815.2 J9.B67(HSOP12-)
PEX_PE6_TXN13: C817.1 ; also on sheet 20
PEX_PE6_TXN13_C: C817.2 J9.B71(HSOP13-)
PEX_PE6_TXN14: C819.1 ; also on sheet 20
PEX_PE6_TXN14_C: C819.2 J9.B75(HSOP14-)
PEX_PE6_TXN15: C821.1 ; also on sheet 20
PEX_PE6_TXN15_C: C821.2 J9.B79(HSOP15-)
PEX_PE6_TXP0: C790.1 ; also on sheet 20
PEX_PE6_TXP0_C: C790.2 J9.B14(HSOP0+)
PEX_PE6_TXP1: C792.1 ; also on sheet 20
PEX_PE6_TXP1_C: C792.2 J9.B19(HSOP1+)
PEX_PE6_TXP2: C794.1 ; also on sheet 20
PEX_PE6_TXP2_C: C794.2 J9.B23(HSOP2+)
PEX_PE6_TXP3: C796.1 ; also on sheet 20
PEX_PE6_TXP3_C: C796.2 J9.B27(HSOP3+)
PEX_PE6_TXP4: C798.1 ; also on sheet 20
PEX_PE6_TXP4_C: C798.2 J9.B33(HSOP4+)
PEX_PE6_TXP5: C800.1 ; also on sheet 20
PEX_PE6_TXP5_C: C800.2 J9.B37(HSOP5+)
PEX_PE6_TXP6: C802.1 ; also on sheet 20
PEX_PE6_TXP6_C: C802.2 J9.B41(HSOP6+)
PEX_PE6_TXP7: C804.1 ; also on sheet 20
PEX_PE6_TXP7_C: C804.2 J9.B45(HSOP7+)
PEX_PE6_TXP8: C806.1 ; also on sheet 20
PEX_PE6_TXP8_C: C806.2 J9.B50(HSOP8+)
PEX_PE6_TXP9: C808.1 ; also on sheet 20
PEX_PE6_TXP9_C: C808.2 J9.B54(HSOP9+)
PEX_PE6_TXP10: C810.1 ; also on sheet 20
PEX_PE6_TXP10_C: C810.2 J9.B58(HSOP10+)
PEX_PE6_TXP11: C812.1 ; also on sheet 20
PEX_PE6_TXP11_C: C812.2 J9.B62(HSOP11+)
PEX_PE6_TXP12: C814.1 ; also on sheet 20
PEX_PE6_TXP12_C: C814.2 J9.B66(HSOP12+)
PEX_PE6_TXP13: C816.1 ; also on sheet 20
PEX_PE6_TXP13_C: C816.2 J9.B70(HSOP13+)
PEX_PE6_TXP14: C818.1 ; also on sheet 20
PEX_PE6_TXP14_C: C818.2 J9.B74(HSOP14+)
PEX_PE6_TXP15: C820.1 ; also on sheet 20
PEX_PE6_TXP15_C: C820.2 J9.B78(HSOP15+)
RST_PCIE_SLOT_2_N: R534.2 ; also on sheet 54
RST_PCIE_SLOT_2_R_N: J5.A11(PERST#) R534.1
RST_PCIE_SLOT_3_N: R542.2 ; also on sheet 54
RST_PCIE_SLOT_3_R_N: J6.A11(PERST#) R542.1
RST_PCIE_SLOT_4_N: R549.2 ; also on sheet 54
RST_PCIE_SLOT_4_R_N: J7.A11(PERST#) R549.1
RST_PCIE_SLOT_5_N: R558.2 ; also on sheet 54
RST_PCIE_SLOT_5_R_N: J8.A11(PERST#) R558.1
RST_PCIE_SLOT_6_N: R566.2 ; also on sheet 54
RST_PCIE_SLOT_6_R_N: J9.A11(PERST#) R566.1
SMB_PE2_SCL: R533.1 ; also on sheet 45
SMB_PE2_SCL_R: J5.B5(SMCLK) R529.2 R533.2
SMB_PE2_SDA: R532.1 ; also on sheet 45
SMB_PE2_SDA_R: J5.B6(SMDATA) R530.2 R532.2
SMB_PE3_SCL: R541.1 ; also on sheet 45
SMB_PE3_SCL_R: J6.B5(SMCLK) R537.2 R541.2
SMB_PE3_SDA: R540.1 ; also on sheet 45
SMB_PE3_SDA_R: J6.B6(SMDATA) R538.2 R540.2
SMB_PE4_SCL: R551.1 ; also on sheet 45
SMB_PE4_SCL_R: J7.B5(SMCLK) R545.2 R551.2
SMB_PE4_SDA: R548.1 ; also on sheet 45
SMB_PE4_SDA_R: J7.B6(SMDATA) R546.2 R548.2
SMB_PE5_SCL: R556.1 ; also on sheet 45
SMB_PE5_SCL_R: J8.B5(SMCLK) R553.2 R556.2
SMB_PE5_SDA: R557.1 ; also on sheet 45
SMB_PE5_SDA_R: J8.B6(SMDATA) R554.2 R557.2
SMB_PE6_SCL: R564.1 ; also on sheet 45
SMB_PE6_SCL_R: J9.B5(SMCLK) R561.2 R564.2
SMB_PE6_SDA: R565.1 ; also on sheet 45
SMB_PE6_SDA_R: J9.B6(SMDATA) R562.2 R565.2
TP_PE_SLOT2_JTAG_TDO: J5.A7(JTAG4)
TP_PE_SLOT2_RSVD_B82: J5.B82(RSVD3)
TP_PE_SLOT3_JTAG_TDO: J6.A7(JTAG4)
TP_PE_SLOT3_RSVD_B82: J6.B82(RSVD3)
TP_PE_SLOT4_JTAG_TDO: J7.A7(JTAG4)
TP_PE_SLOT4_RSVD_B82: J7.B82(RSVD3)
TP_PE_SLOT5_JTAG_TDO: J8.A7(JTAG4)
TP_PE_SLOT5_RSVD_B82: J8.B82(RSVD3)
TP_PE_SLOT6_JTAG_TDO: J9.A7(JTAG4)
TP_PE_SLOT6_RSVD_B82: J9.B82(RSVD3)
TP_SLOT2_JTAG_TCK: J5.A5(JTAG2)
TP_SLOT2_JTAG_TDI: J5.A6(JTAG3)
TP_SLOT2_JTAG_TMS: J5.A8(JTAG5)
TP_SLOT2_JTAG_TRST_N: J5.B9(JTAG1)
TP_SLOT2_RSVD_A19: J5.A19(RSVD4)
TP_SLOT2_RSVD_A32: J5.A32(RSVD5)
TP_SLOT2_RSVD_A33: J5.A33(RSVD6)
TP_SLOT2_RSVD_A50: J5.A50(RSVD7)
TP_SLOT2_RSVD_B30: J5.B30(RSVD2)
TP_SLOT2_WAKE_N: J5.B11(WAKE_N)
TP_SLOT3_JTAG_TCK: J6.A5(JTAG2)
TP_SLOT3_JTAG_TDI: J6.A6(JTAG3)
TP_SLOT3_JTAG_TMS: J6.A8(JTAG5)
TP_SLOT3_JTAG_TRST_N: J6.B9(JTAG1)
TP_SLOT3_RSVD_A19: J6.A19(RSVD4)
TP_SLOT3_RSVD_A32: J6.A32(RSVD5)
TP_SLOT3_RSVD_A33: J6.A33(RSVD6)
TP_SLOT3_RSVD_A50: J6.A50(RSVD7)
TP_SLOT3_RSVD_B30: J6.B30(RSVD2)
TP_SLOT3_WAKE_N: J6.B11(WAKE_N)
TP_SLOT4_JTAG_TCK: J7.A5(JTAG2)
TP_SLOT4_JTAG_TDI: J7.A6(JTAG3)
TP_SLOT4_JTAG_TMS: J7.A8(JTAG5)
TP_SLOT4_JTAG_TRST_N: J7.B9(JTAG1)
TP_SLOT4_RSVD_A19: J7.A19(RSVD4)
TP_SLOT4_RSVD_A32: J7.A32(RSVD5)
TP_SLOT4_RSVD_A33: J7.A33(RSVD6)
TP_SLOT4_RSVD_A50: J7.A50(RSVD7)
TP_SLOT4_RSVD_B30: J7.B30(RSVD2)
TP_SLOT4_WAKE_N: J7.B11(WAKE_N)
TP_SLOT5_JTAG_TCK: J8.A5(JTAG2)
TP_SLOT5_JTAG_TDI: J8.A6(JTAG3)
TP_SLOT5_JTAG_TMS: J8.A8(JTAG5)
TP_SLOT5_JTAG_TRST_N: J8.B9(JTAG1)
TP_SLOT5_RSVD_A19: J8.A19(RSVD4)
TP_SLOT5_RSVD_A32: J8.A32(RSVD5)
TP_SLOT5_RSVD_A33: J8.A33(RSVD6)
TP_SLOT5_RSVD_A50: J8.A50(RSVD7)
TP_SLOT5_RSVD_B30: J8.B30(RSVD2)
TP_SLOT5_WAKE_N: J8.B11(WAKE_N)
TP_SLOT6_JTAG_TCK: J9.A5(JTAG2)
TP_SLOT6_JTAG_TDI: J9.A6(JTAG3)
TP_SLOT6_JTAG_TMS: J9.A8(JTAG5)
TP_SLOT6_JTAG_TRST_N: J9.B9(JTAG1)
TP_SLOT6_RSVD_A19: J9.A19(RSVD4)
TP_SLOT6_RSVD_A32: J9.A32(RSVD5)
TP_SLOT6_RSVD_A33: J9.A33(RSVD6)
TP_SLOT6_RSVD_A50: J9.A50(RSVD7)
TP_SLOT6_RSVD_B30: J9.B30(RSVD2)
TP_SLOT6_WAKE_N: J9.B11(WAKE_N)
